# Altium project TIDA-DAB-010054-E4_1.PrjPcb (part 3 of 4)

## Sheet TIDA-DAB-010054-E4_GateDriverPrimHB2.SchDoc
size 431 x 279 mm; Date: Not shown in title block; ApprovedBy: Not shown in title block; CheckedBy: Not shown in title block; Author: Not shown in title block; CompanyName: Not shown in title block; Engineer: Not shown in title block; Organization: Not shown in title block; Address1: Not shown in title block; Address2: Not shown in title block; Address3: Not shown in title block; Address4: Not shown in title block; DocumentNumber: 1; Revision: Use project parameter SCH_Rev; SheetNumber: 6; SheetTotal: 11; PageSetup: Record=PageOptions¦CenterHorizontal=True¦CenterVertical=True¦PrintScale=1.00¦XCorrection=1.00¦YCorrection=1.00¦PrintKind=0¦BorderSize=5000000¦LeftOffset=0¦BottomOffset=0¦Orientation=2¦PaperLength=1000¦PaperWidth=1000¦Scale=100¦PaperSource=15¦PrintQuality=600¦MediaType=1¦DitherType=10¦PaperKind=Letter¦PrintScaleMode=1
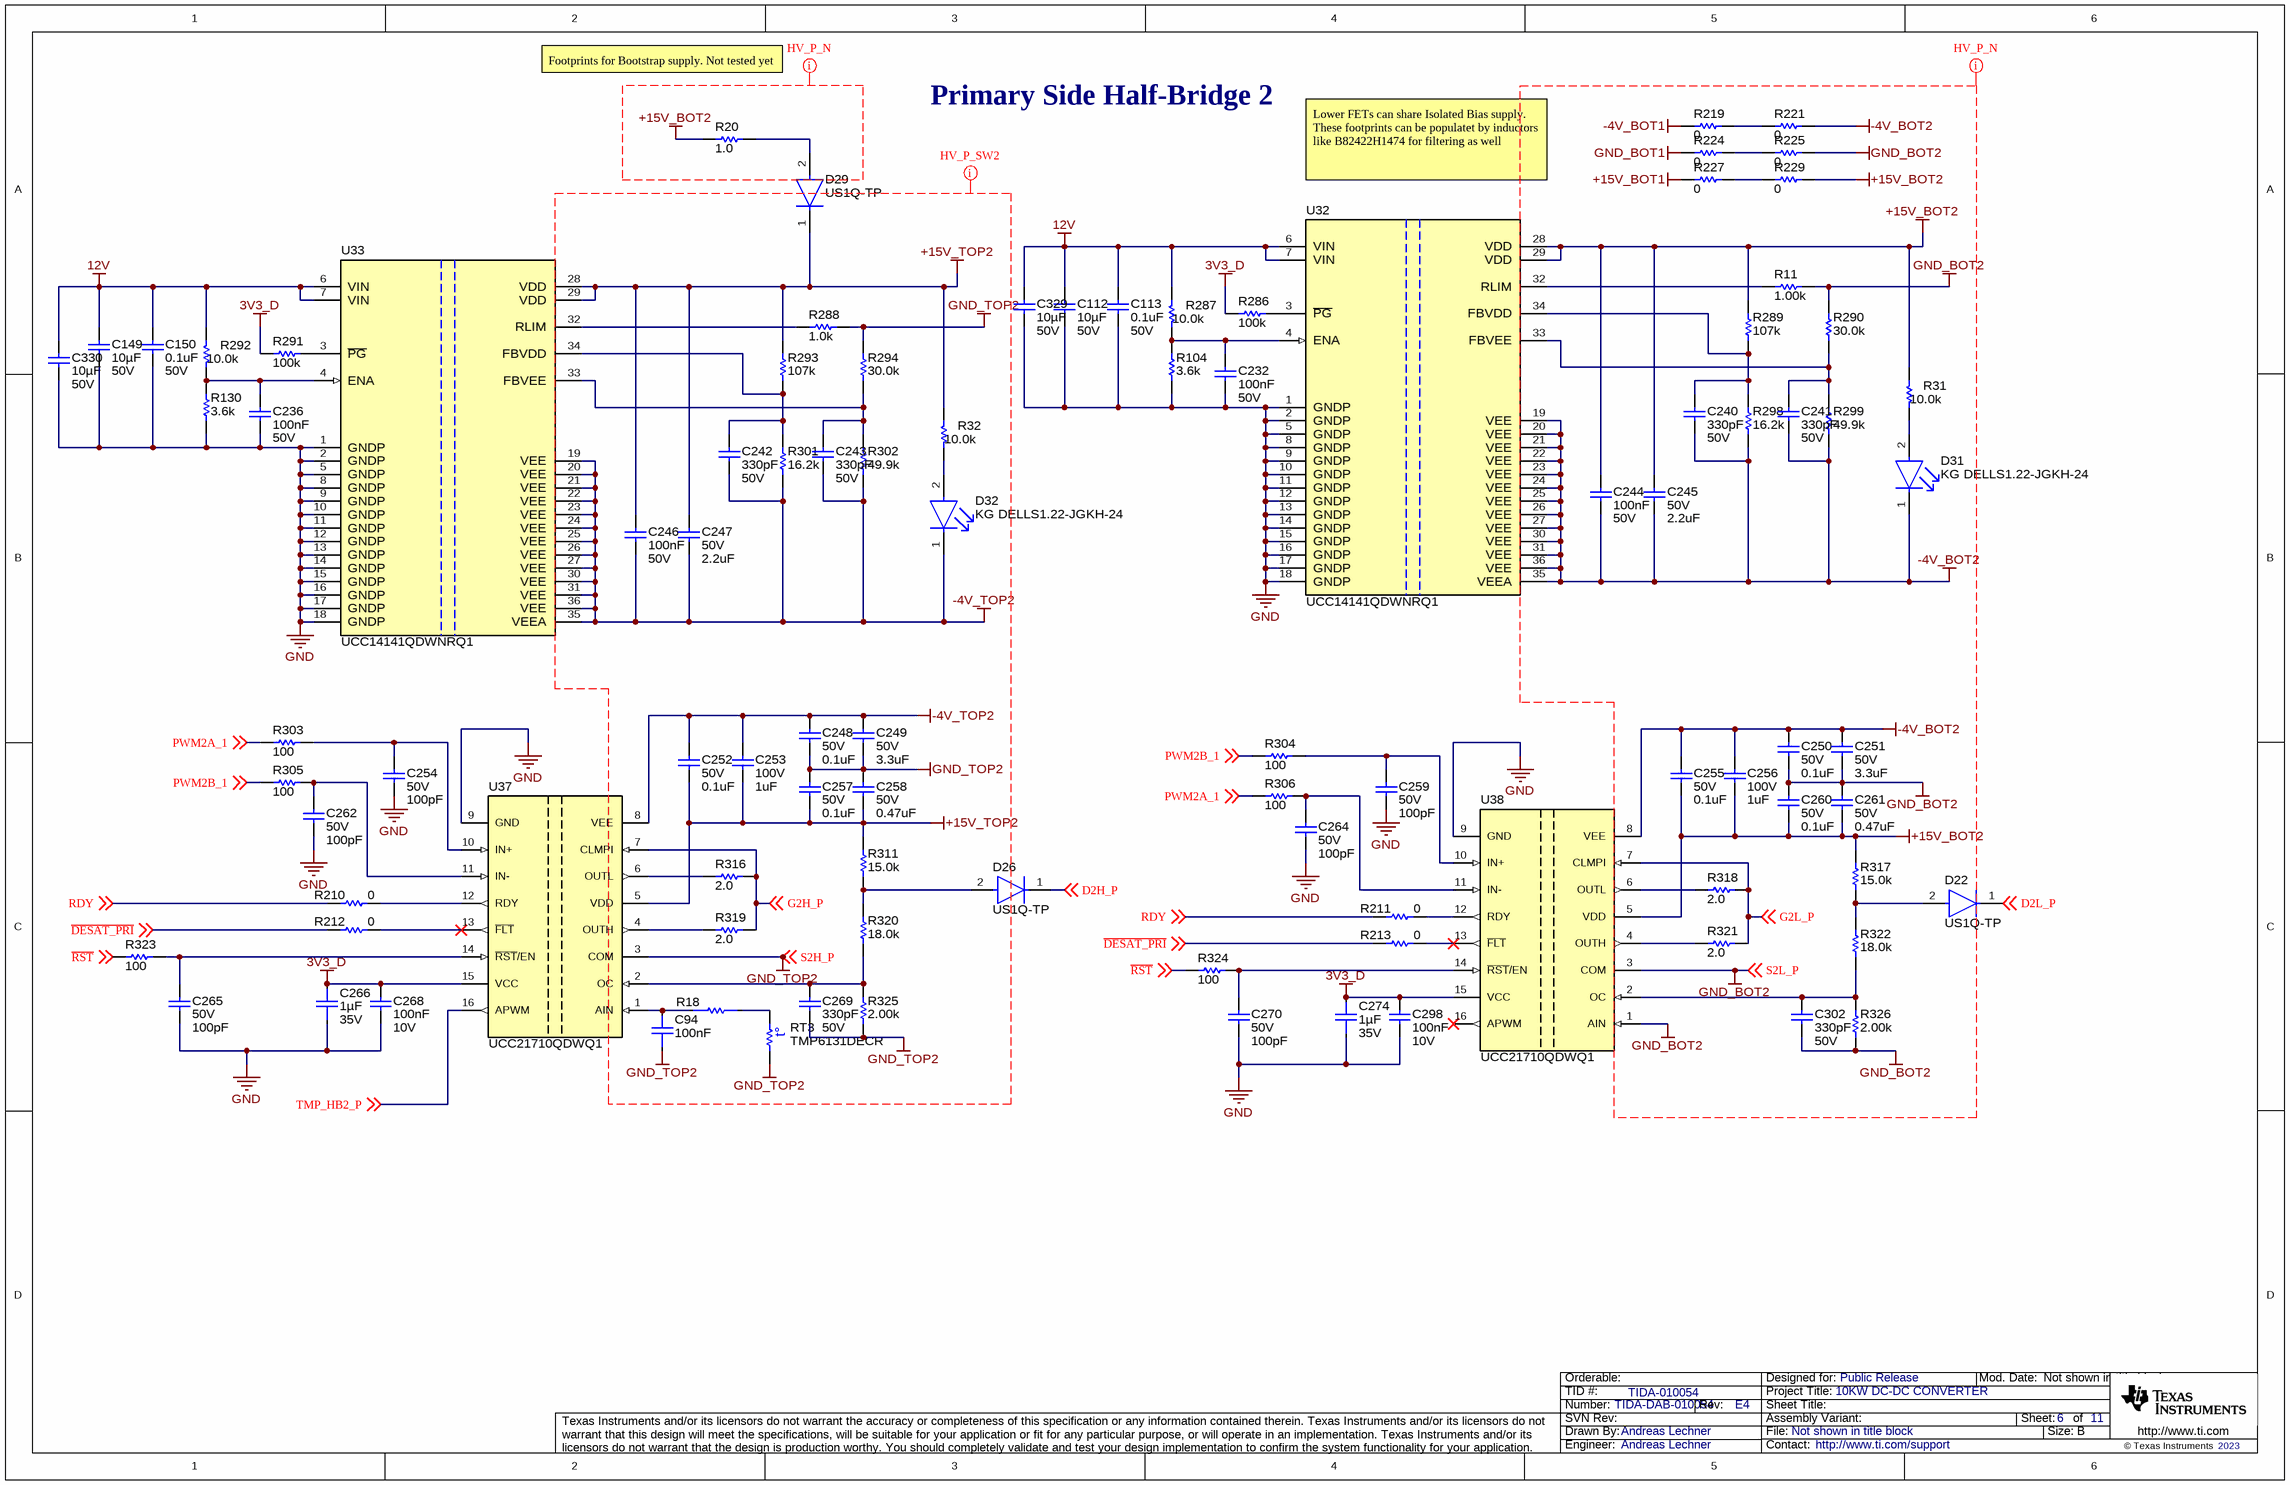
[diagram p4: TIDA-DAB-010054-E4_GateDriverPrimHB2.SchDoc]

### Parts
C94  Cap_F: 100nF  [FP-CL10B104KA8VPJC_0603-MFG]  (hidden comment: CL10B104KA8VPJC)
C112  ValueDisplayed: 10µF  VDC_V: 50V  [1206_190L]  (hidden comment: CGA5L1X7R1H106K160AC)
C113  value 0.1uF  VDC_V: 50V  [0603]  (hidden comment: CGA3E2X7R1H104K080AA)
C149  ValueDisplayed: 10µF  VDC_V: 50V  [1206_190L]  (hidden comment: CGA5L1X7R1H106K160AC)
C150  value 0.1uF  VDC_V: 50V  [0603]  (hidden comment: CGA3E2X7R1H104K080AA)
C232  Cap_F: 100nF  VDC_V: 50V  [0603]  (hidden comment: CGA3E2X7R1H104K080AA)
C236  Cap_F: 100nF  VDC_V: 50V  [0603]  (hidden comment: CGA3E2X7R1H104K080AA)
C240  Cap_F: 330pF  VDC_V: 50V  [0603]  (hidden comment: C0603C331K5RACTU)
C241  Cap_F: 330pF  VDC_V: 50V  [0603]  (hidden comment: C0603C331K5RACTU)
C242  Cap_F: 330pF  VDC_V: 50V  [0603]  (hidden comment: C0603C331K5RACTU)
C243  Cap_F: 330pF  VDC_V: 50V  [0603]  (hidden comment: C0603C331K5RACTU)
C244  Cap_F: 100nF  VDC_V: 50V  [0603]  (hidden comment: CGA3E2X7R1H104K080AA)
C245  VDC_V: 50V  ValueDisplayed: 2.2uF  [1206_180L]  (hidden comment: C3216X7R1H225K160AB)
C246  Cap_F: 100nF  VDC_V: 50V  [0603]  (hidden comment: CGA3E2X7R1H104K080AA)
C247  VDC_V: 50V  ValueDisplayed: 2.2uF  [1206_180L]  (hidden comment: C3216X7R1H225K160AB)
C248  VDC_V: 50V  ValueDisplayed: 0.1uF  [1206L]  (hidden comment: C1206C104K5RACTU)
C249  VDC_V: 50V  ValueDisplayed: 3.3uF  [1206_180L]  (hidden comment: C3216X5R1H335K160AB)
C250  VDC_V: 50V  ValueDisplayed: 0.1uF  [1206L]  (hidden comment: C1206C104K5RACTU)
C251  VDC_V: 50V  ValueDisplayed: 3.3uF  [1206_180L]  (hidden comment: C3216X5R1H335K160AB)
C252  VDC_V: 50V  ValueDisplayed: 0.1uF  [1206L]  (hidden comment: C1206C104K5RACTU)
C253  VDC_V: 100V  ValueDisplayed: 1uF  [1206_180L]  (hidden comment: C3216X7R2A105K160AA)
C254  VDC_V: 50V  ValueDisplayed: 100pF  [0603]  (hidden comment: C0603C101F5GACTU)
C255  VDC_V: 50V  ValueDisplayed: 0.1uF  [1206L]  (hidden comment: C1206C104K5RACTU)
C256  VDC_V: 100V  ValueDisplayed: 1uF  [1206_180L]  (hidden comment: C3216X7R2A105K160AA)
C257  VDC_V: 50V  ValueDisplayed: 0.1uF  [1206L]  (hidden comment: C1206C104K5RACTU)
C258  VDC_V: 50V  ValueDisplayed: 0.47uF  [1206_180L]  (hidden comment: C3216X7R1H474K160AA)
C259  VDC_V: 50V  ValueDisplayed: 100pF  [0603]  (hidden comment: C0603C101F5GACTU)
C260  VDC_V: 50V  ValueDisplayed: 0.1uF  [1206L]  (hidden comment: C1206C104K5RACTU)
C261  VDC_V: 50V  ValueDisplayed: 0.47uF  [1206_180L]  (hidden comment: C3216X7R1H474K160AA)
C262  VDC_V: 50V  ValueDisplayed: 100pF  [0603]  (hidden comment: C0603C101F5GACTU)
C264  VDC_V: 50V  ValueDisplayed: 100pF  [0603]  (hidden comment: C0603C101F5GACTU)
C265  VDC_V: 50V  ValueDisplayed: 100pF  [0603]  (hidden comment: C0603C101F5GACTU)
C266  Cap_F: 1µF  VDC_V: 35V  [FP-CL10B105KL9VPJC_0603-MFG]  (hidden comment: CL10B105KL9VPJC)
C268  Cap_F: 100nF  VDC_V: 10V  [0603]  (hidden comment: 0603ZC104KAT2A)
C269  Cap_F: 330pF  VDC_V: 50V  [0603]  (hidden comment: C0603C331K5RACTU)
C270  VDC_V: 50V  ValueDisplayed: 100pF  [0603]  (hidden comment: C0603C101F5GACTU)
C274  Cap_F: 1µF  VDC_V: 35V  [FP-CL10B105KL9VPJC_0603-MFG]  (hidden comment: CL10B105KL9VPJC)
C298  Cap_F: 100nF  VDC_V: 10V  [0603]  (hidden comment: 0603ZC104KAT2A)
C302  Cap_F: 330pF  VDC_V: 50V  [0603]  (hidden comment: C0603C331K5RACTU)
C329  ValueDisplayed: 10µF  VDC_V: 50V  [1206_190L]  (hidden comment: CGA5L1X7R1H106K160AC)
C330  ValueDisplayed: 10µF  VDC_V: 50V  [1206_190L]  (hidden comment: CGA5L1X7R1H106K160AC)
D22  US1Q-TP  [FP-US1Q-TP_SMA-MFG]
D26  US1Q-TP  [FP-US1Q-TP_SMA-MFG]
D29  US1Q-TP  [FP-US1Q-TP_SMA-MFG]
D31  KG DELLS1.22-JGKH-24  [FP-KG DELLS1.22-JGKH-24_0603-MFG]
D32  KG DELLS1.22-JGKH-24  [FP-KG DELLS1.22-JGKH-24_0603-MFG]
R11  ValueDisplayed: 1.00k  [0805_HV]  (hidden comment: ERJ-P06F1001V)
R18  CH0603-10RJFTA  [FP-CH0603-10RJFTA_0603-MFG]  (value not drawn)
R20  ValueDisplayed: 1.0  [1206]  (hidden comment: CRM1206-JW-1R0ELF)
R31  ValueDisplayed: 10.0k  [0603]  (hidden comment: CRCW060310K0FKEA)
R32  ValueDisplayed: 10.0k  [0603]  (hidden comment: CRCW060310K0FKEA)
R104  ValueDisplayed: 3.6k  [0603]  (hidden comment: RC0603JR-073K6L)
R130  ValueDisplayed: 3.6k  [0603]  (hidden comment: RC0603JR-073K6L)
R210  ValueDisplayed: 0  [0603S]  (hidden comment: RMCF0603ZT0R00)
R211  ValueDisplayed: 0  [0603S]  (hidden comment: RMCF0603ZT0R00)
R212  ValueDisplayed: 0  [0603S]  (hidden comment: RMCF0603ZT0R00)
R213  ValueDisplayed: 0  [0603S]  (hidden comment: RMCF0603ZT0R00)
R219  ValueDisplayed: 0  [1210]  (hidden comment: CRCW12100000Z0EA)
R221  ValueDisplayed: 0  [1210]  (hidden comment: CRCW12100000Z0EA)
R224  ValueDisplayed: 0  [1210]  (hidden comment: CRCW12100000Z0EA)
R225  ValueDisplayed: 0  [1210]  (hidden comment: CRCW12100000Z0EA)
R227  ValueDisplayed: 0  [1210]  (hidden comment: CRCW12100000Z0EA)
R229  ValueDisplayed: 0  [1210]  (hidden comment: CRCW12100000Z0EA)
R286  ValueDisplayed: 100k  [0603]  (hidden comment: CRCW0603100KJNEA)
R287  ValueDisplayed: 10.0k  [0603]  (hidden comment: CRCW060310K0FKEA)
R288  ValueDisplayed: 1.0k  [0603]  (hidden comment: RCA06031K00JNEA)
R289  ValueDisplayed: 107k  [0603]  (hidden comment: RT0603BRD07107KL)
R290  ValueDisplayed: 30.0k  [0603]  (hidden comment: RG1608P-303-B-T5)
R291  ValueDisplayed: 100k  [0603]  (hidden comment: CRCW0603100KJNEA)
R292  ValueDisplayed: 10.0k  [0603]  (hidden comment: CRCW060310K0FKEA)
R293  ValueDisplayed: 107k  [0603]  (hidden comment: RT0603BRD07107KL)
R294  ValueDisplayed: 30.0k  [0603]  (hidden comment: RG1608P-303-B-T5)
R298  ValueDisplayed: 16.2k  [0603]  (hidden comment: RT0603BRD0716K2L)
R299  ValueDisplayed: 49.9k  [0603]  (hidden comment: RT0603BRD0749K9L)
R301  ValueDisplayed: 16.2k  [0603]  (hidden comment: RT0603BRD0716K2L)
R302  ValueDisplayed: 49.9k  [0603]  (hidden comment: RT0603BRD0749K9L)
R303  ValueDisplayed: 100  [0603]  (hidden comment: CRCW0603100RJNEA)
R304  ValueDisplayed: 100  [0603]  (hidden comment: CRCW0603100RJNEA)
R305  ValueDisplayed: 100  [0603]  (hidden comment: CRCW0603100RJNEA)
R306  ValueDisplayed: 100  [0603]  (hidden comment: CRCW0603100RJNEA)
R311  ValueDisplayed: 15.0k  [0603]  (hidden comment: RC0603FR-0715KL)
R316  ValueDisplayed: 2.0  [1206]  (hidden comment: CRCW12062R00JNEA)
R317  ValueDisplayed: 15.0k  [0603]  (hidden comment: RC0603FR-0715KL)
R318  ValueDisplayed: 2.0  [1206]  (hidden comment: CRCW12062R00JNEA)
R319  ValueDisplayed: 2.0  [1206]  (hidden comment: CRCW12062R00JNEA)
R320  ValueDisplayed: 18.0k  [0603]  (hidden comment: ERJ3EKF1802V)
R321  ValueDisplayed: 2.0  [1206]  (hidden comment: CRCW12062R00JNEA)
R322  ValueDisplayed: 18.0k  [0603]  (hidden comment: ERJ3EKF1802V)
R323  ValueDisplayed: 100  [0603]  (hidden comment: CRCW0603100RJNEA)
R324  ValueDisplayed: 100  [0603]  (hidden comment: CRCW0603100RJNEA)
R325  ValueDisplayed: 2.00k  [0603]  (hidden comment: RC0603FR-072KL)
R326  ValueDisplayed: 2.00k  [0603]  (hidden comment: RC0603FR-072KL)
RT3  TMP6131DECR  [DEC0002A]
U32  UCC14141QDWNRQ1  [DWJ0036A-MFG]
U33  UCC14141QDWNRQ1  [DWJ0036A-MFG]
U37  UCC21710QDWQ1  [DW0016B_HV]
U38  UCC21710QDWQ1  [DW0016B_HV]

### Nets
3V3_D: C266.2 C268.2 C274.2 C298.2 R286.1 R291.1 U37.15(VCC) U38.15(VCC)
12V: C112.1 C113.1 C149.1 C150.1 C329.1 C330.1 R287.2 R292.2 U32.6(VIN) U32.7(VIN) U33.6(VIN) U33.7(VIN)
+15V_BOT1: R227.1
+15V_BOT2: C244.1 C245.1 C255.2 C256.2 C260.2 C261.2 R20.1 R31.2 R229.2 R289.2 R317.2 U32.28(VDD) U32.29(VDD) U38.5(VDD)
+15V_TOP2: C246.1 C247.1 C252.2 C253.2 C257.2 C258.2 D29.1(CATHODE) R32.2 R293.2 R311.2 U33.28(VDD) U33.29(VDD) U37.5(VDD)
-4V_BOT1: R219.1
-4V_BOT2: C240.2 C241.2 C244.2 C245.2 C250.1 C251.1 C255.1 C256.1 D31.1(CATHODE) R221.2 R298.1 R299.1 U32.19(VEE) U32.20(VEE) U32.21(VEE) U32.22(VEE) U32.23(VEE) U32.24(VEE) U32.25(VEE) U32.26(VEE) U32.27(VEE) U32.30(VEE) U32.31(VEE) U32.35(VEEA) U32.36(VEE) U38.8(VEE)
-4V_TOP2: C242.2 C243.2 C246.2 C247.2 C248.1 C249.1 C252.1 C253.1 D32.1(CATHODE) R301.1 R302.1 U33.19(VEE) U33.20(VEE) U33.21(VEE) U33.22(VEE) U33.23(VEE) U33.24(VEE) U33.25(VEE) U33.26(VEE) U33.27(VEE) U33.30(VEE) U33.31(VEE) U33.35(VEEA) U33.36(VEE) U37.8(VEE)
GND: C112.2 C113.2 C149.2 C150.2 C232.2 C236.2 C254.2 C259.2 C262.2 C264.2 C265.2 C266.1 C268.1 C270.2 C274.1 C298.1 C329.2 C330.2 R104.1 R130.1 U32.1(GNDP) U32.2(GNDP) U32.5(GNDP) U32.8(GNDP) U32.9(GNDP) U32.10(GNDP) U32.11(GNDP) U32.12(GNDP) U32.13(GNDP) U32.14(GNDP) U32.15(GNDP) U32.16(GNDP) U32.17(GNDP) U32.18(GNDP) U33.1(GNDP) U33.2(GNDP) U33.5(GNDP) U33.8(GNDP) U33.9(GNDP) U33.10(GNDP) U33.11(GNDP) U33.12(GNDP) U33.13(GNDP) U33.14(GNDP) U33.15(GNDP) U33.16(GNDP) U33.17(GNDP) U33.18(GNDP) U37.9(GND) U38.9(GND)
GND_BOT1: R224.1
GND_BOT2: C250.2 C251.2 C260.1 C261.1 C302.2 R11.2 R225.2 R290.2 R326.1 U38.1(AIN) U38.3(COM) ; off-sheet S2L_P  [also labelled S2L_P]
GND_TOP2: C94.1 C248.2 C249.2 C257.1 C258.1 C269.2 R288.2 R294.2 R325.1 RT3.1 U37.3(COM) ; off-sheet S2H_P  [also labelled S2H_P]
~{DESAT_PRI}: R212.1 R213.1 ; off-sheet ~{DESAT_PRI}
~{RST}: R323.1 R324.1 ; off-sheet ~{RST}
D2H_P: D26.1(CATHODE) ; off-sheet D2H_P  [project net D1H_P]
D2L_P: D22.1(CATHODE) ; off-sheet D2L_P
G2H_P: R316.2 R319.2 U37.7(CLMPI) ; off-sheet G2H_P
G2L_P: R318.2 R321.2 U38.7(CLMPI) ; off-sheet G2L_P
PWM2A_1: R303.1 R306.1 ; off-sheet PWM2A_1
PWM2B_1: R304.1 R305.1 ; off-sheet PWM2B_1
RDY: R210.1 R211.1 ; off-sheet RDY
TMP_HB2_P: U37.16(APWM) ; off-sheet TMP_HB2_P
NetC94_2: C94.2 R18.1 U37.1(AIN)
NetC232_1: C232.1 R104.2 R287.1 U32.4(ENA)
NetC236_1: C236.1 R130.2 R292.1 U33.4(ENA)
NetC240_1: C240.1 R289.1 R298.2 U32.34(FBVDD)
NetC241_1: C241.1 R290.1 R299.2 U32.33(FBVEE)
NetC242_1: C242.1 R293.1 R301.2 U33.34(FBVDD)
NetC243_1: C243.1 R294.1 R302.2 U33.33(FBVEE)
NetC254_1: C254.1 R303.2 U37.10(IN+)
NetC259_1: C259.1 R304.2 U38.10(IN+)
NetC262_1: C262.1 R305.2 U37.11(IN-)
NetC264_1: C264.1 R306.2 U38.11(IN-)
NetC265_1: C265.1 R323.2 U37.14(~{RST}/EN)
NetC269_1: C269.1 R320.1 R325.2 U37.2(OC)
NetC270_1: C270.1 R324.2 U38.14(~{RST}/EN)
NetC302_1: C302.1 R322.1 R326.2 U38.2(OC)
NetD22_2: D22.2(ANODE) R317.1 R322.2
NetD26_2: D26.2(ANODE) R311.1 R320.2
NetD29_2: D29.2(ANODE) R20.2
NetD31_2: D31.2(ANODE) R31.1
NetD32_2: D32.2(ANODE) R32.1
NetR11_1: R11.1 U32.32(RLIM)
NetR18_2: R18.2 RT3.2
NetR210_2: R210.2 U37.12(RDY)
NetR211_2: R211.2 U38.12(RDY)
NetR212_2: R212.2 U37.13(~{FLT})
NetR213_2: R213.2 U38.13(~{FLT})
NetR219_2: R219.2 R221.1
NetR224_2: R224.2 R225.1
NetR227_2: R227.2 R229.1
NetR286_2: R286.2 U32.3(~{PG})
NetR288_1: R288.1 U33.32(RLIM)
NetR291_2: R291.2 U33.3(~{PG})
NetR316_1: R316.1 U37.6(OUTL)
NetR318_1: R318.1 U38.6(OUTL)
NetR319_1: R319.1 U37.4(OUTH)
NetR321_1: R321.1 U38.4(OUTH)

Not connected (* = marked no-connect by the designer): U38 16(APWM)*

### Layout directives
net class HV_P_SW2: +15V_TOP2, -4V_TOP2, G2H_P, GND_TOP2, S2H_P
net class HV_P_N: +15V_BOT1, +15V_BOT2, -4V_BOT1, -4V_BOT2, G2L_P, GND, GND_BOT1, GND_BOT2, S2L_P

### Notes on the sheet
- Footprints for Bootstrap supply. Not tested yet
- Primary Side Half-Bridge 2
- Lower FETs can share Isolated Bias supply.
  These footprints can be populatet by inductors  like B82422H1474 for filtering as well

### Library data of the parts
C94 = CMP-0121051-1: Automotive CAP, 100㎋, 25V, ±10%, X7R, 0603, 5mm Bending; Manufacturer: Samsung; AEC Grade: Grade 1; AEC Qualified: Yes; SizeZ_mm: 0.9mm; TempCo: 15%; Value: 100nF
C112 C149 C329 C330 = CMP-0085950-1: CAP, CERM, 10 µF, 50 V,+/- 10%, X7R, AEC-Q200 Grade 1, 1206; Manufacturer: TDK; SizeZ_mm: 1.9; Value: 10uF; Cap_Case: 1206; AEC Grade: 1; TaMin_C: -55°C; U/M: EA; SizeArea_mm2: 5.12; TaMax_C: 125°C; AEC Qualified: Y; AEC Category: Q200; SizeX_mm: 3.2; SizeY_mm: 1.6; Polarized: N; SizeAreaWB_mm2: 10.92
C113 C150 = CMP-0007078-4: CAP, CERM, 0.1 uF, 50 V, +/- 10%, X7R, AEC-Q200 Grade 1, 0603; Manufacturer: TDK; TaMin_C: -55°C; ESR_ohm: 29.6m; Polarized: N; SizeAreaWB_mm2: 4.68; Value1: 0.0296 ohm; U/M: EA; TaMax_C: 125°C; SizeZ_mm: 1; SizeX_mm: 1.6; SizeY_mm: 0.8; SizeArea_mm2: 1.28; AEC Qualified: Y; Cap_F: 100nF; IRMS_A: 971.99mA; AEC Category: Q200
C232 C236 C244 C246 = CMP-0007078-4: CAP, CERM, 0.1 uF, 50 V, +/- 10%, X7R, AEC-Q200 Grade 1, 0603; Manufacturer: TDK; TaMin_C: -55°C; ESR_ohm: 29.6m; Polarized: N; SizeAreaWB_mm2: 4.68; Value1: 0.0296 ohm; U/M: EA; Value: 0.1uF; TaMax_C: 125°C; SizeZ_mm: 1; SizeX_mm: 1.6; SizeY_mm: 0.8; SizeArea_mm2: 1.28; AEC Qualified: Y; IRMS_A: 971.99mA; AEC Category: Q200
C240-C243 C269 C302 = CMP-0006921-4: CAP, CERM, 330 pF, 50 V, +/- 10%, X7R, 0603; Manufacturer: Kemet; TaMin_C: -55°C; Polarized: N; SizeAreaWB_mm2: 4.68; Value1: Unknown; U/M: EA; Value: 330pF; TaMax_C: 125°C; SizeZ_mm: 1; SizeX_mm: 1.6; SizeY_mm: 0.8; SizeArea_mm2: 1.28; AEC Category: Q200
C245 C247 = CMP-0008698-2: CAP, CERM, 2.2 uF, 50 V, +/- 10%, X7R, 1206; Manufacturer: TDK; TaMin_C: -55°C; ESR_ohm: 5.887m; Polarized: N; SizeAreaWB_mm2: 10.92; Value1: 0.005887 ohm; U/M: EA; Value: 2.2uF; TaMax_C: 125°C; SizeZ_mm: 1.8; SizeX_mm: 3.2; SizeY_mm: 1.6; Cap_Case: 1206_180; SizeArea_mm2: 5.12; Cap_F: 2.2µF; IRMS_A: 2.9923A; AEC Category: Q200
C248 C250 C252 C255 C257 C260 = CMP-0008586-2: CAP, CERM, 0.1 uF, 50 V, +/- 10%, X7R, 1206; Manufacturer: Kemet; TaMin_C: -55°C; ESR_ohm: 59m; Polarized: N; SizeAreaWB_mm2: 10.92; Value1: 0.059 ohm; U/M: EA; Value: 0.1uF; TaMax_C: 125°C; SizeZ_mm: 1.35; SizeX_mm: 3.2; SizeY_mm: 1.6; Cap_Case: 1206; SizeArea_mm2: 5.12; Cap_F: 100nF; IRMS_A: 1.2A; AEC Category: Q200
C249 C251 = CMP-0008661-2: CAP, CERM, 3.3 uF, 50 V, +/- 10%, X5R, 1206; Manufacturer: TDK; TaMin_C: -55°C; ESR_ohm: 4.773m; Polarized: N; SizeAreaWB_mm2: 10.92; Value1: 0.004773 ohm; U/M: EA; Value: 3.3uF; TaMax_C: 85°C; SizeZ_mm: 1.8; SizeX_mm: 3.2; SizeY_mm: 1.6; Cap_Case: 1206_180; SizeArea_mm2: 5.12; Cap_F: 3.3µF; IRMS_A: 3.3221A; AEC Category: Q200
C253 C256 = CMP-0008710-2: CAP, CERM, 1 uF, 100 V, +/- 10%, X7R, 1206; Manufacturer: TDK; TaMin_C: -55°C; ESR_ohm: 4.575m; Polarized: N; SizeAreaWB_mm2: 10.92; Value1: 0.004575 ohm; U/M: EA; Value: 1uF; TaMax_C: 125°C; SizeZ_mm: 1.8; SizeX_mm: 3.2; SizeY_mm: 1.6; Cap_Case: 1206_180; SizeArea_mm2: 5.12; Cap_F: 1µF; IRMS_A: 3.3964A; AEC Category: Q200
C254 C259 C262 C264 C265 C270 = CMP-0080091-1: CAP, CERM, 100 pF, 50 V,+/- 1%, C0G/NP0, 0603; Manufacturer: Kemet; SizeAreaWB_mm2: 4.68; SizeArea_mm2: 1.28; AEC Qualified: N; AEC Category: Q200; Value: 100pF; TaMax_C: 125°C; SizeZ_mm: 1; Green_REACh: Passed; TaMin_C: -55°C; SizeY_mm: 0.8; Green_Lifecycle: Active; U/M: EA; SizeX_mm: 1.6
C258 C261 = CMP-0008701-2: CAP, CERM, 0.47 uF, 50 V, +/- 10%, X7R, 1206; Manufacturer: TDK; TaMin_C: -55°C; ESR_ohm: 9.426m; Polarized: N; SizeAreaWB_mm2: 10.92; Value1: 0.009426 ohm; U/M: EA; Value: 0.47uF; TaMax_C: 125°C; SizeZ_mm: 1.8; SizeX_mm: 3.2; SizeY_mm: 1.6; Cap_Case: 1206_180; SizeArea_mm2: 5.12; Cap_F: 470nF; IRMS_A: 2.3705A; AEC Category: Q200
C266 C274 = CMP-0121053-1: Automotive CAP, 1㎌, 35V, ±10%, X7R, 0603, 5mm Bending; Manufacturer: Samsung; AEC Grade: Grade 1; AEC Qualified: Yes; SizeZ_mm: 1mm; TempCo: 15%; ValueDisplayed: 1uF; Value: 1µF
C268 C298 = CMP-0006815-4: CAP, CERM, 0.1 uF, 10 V, +/- 10%, X7R, 0603; Manufacturer: AVX; TaMin_C: -55°C; Polarized: N; SizeAreaWB_mm2: 4.68; Value1: Unknown; U/M: EA; Value: 0.1uF; TaMax_C: 125°C; SizeZ_mm: 1; SizeX_mm: 1.6; SizeY_mm: 0.8; SizeArea_mm2: 1.28; AEC Category: Q200
D22 D26 D29 = CMP-0095286-1: Diode Standard 1200 V 1A Surface Mount DO-214AC (SMA); Manufacturer: MCC; Cap_F: 45pF; Max Surge Forward Current: 30A; SizeZ_mm: 2.44mm; TJmax_C: 150°C; Vr_V: 1.2kV; Peak Reverse Current: 5uA; AEC Qualified: No
D31 D32 = CMP-0093310-1: Standard LEDs - SMD Green TOPLED E 1608; Manufacturer: Osram Opto; AEC Grade: Grade 2; LambdaP: 572nm; SizeZ_mm: 0.7mm; LuminousFlux_PhiV: 0.016-0.0295lm; Luminous Intensity: 4.5-9.7mcd; LambdaD: 570nm; Tjmax_C: 125°C; Angle: 120°; Led Orientation: Top View; Forward Current: 2mA; Vf_V: 1.8V; AEC Qualified: Yes; Vr_V: 12V
R11 = CMP-0021848-2: RES, 1.00 k, 1%, 0.25 W, 0805; Manufacturer: Panasonic; Power_W: 250mW; TempCo: 100 ppm/C; Value_Code: 1k00; U/M: EA; Value: 1.00k; EIA_Code: E96; Res_ohm: 1k; SizeX_mm: 2; SizeY_mm: 1.25; SizeZ_mm: 1.45; Value2: 0.25W; SizeArea_mm2: 2.5; VDC_V: 400V; AEC Category: Q200
R18 = CMP-0091849-1: Res Thin Film 0603 10Ohm 5% 1/8W ±100ppm/°C Molded T/R; Manufacturer: Vishay; SizeZ_mm: 0.627mm; Power_W: 125mW; AEC Qualified: No; Value: 10; VDC_V: 50V
R20 = CMP-0018745-2: RES, 1.0, 5%, 0.5 W, 1206; Manufacturer: Bourns; Power_W: 500mW; TempCo: 150 ppm/C; Value_Code: 1R00; U/M: EA; Value: 1.0; EIA_Code: E24; Res_ohm: 1; SizeX_mm: 3.2; SizeY_mm: 1.6; SizeZ_mm: 1.35; Value2: 0.5W; SizeArea_mm2: 5.12; VDC_V: 1V; AEC Category: Q200
R31 R32 R287 R292 = CMP-0021998-4: RES, 10.0 k, 1%, 0.1 W, AEC-Q200 Grade 0, 0603; Manufacturer: Vishay-Dale; Value: 10.0k; Res_ohm: 10k; Value_Code: 10k0; Power_W: 100mW; Value2: 0.1W; VDC_V: 75V; TempCo: 100 ppm/C; SizeArea_mm2: 1.28; SizeX_mm: 1.6; SizeY_mm: 0.8; SizeZ_mm: 1; EIA_Code: E96; AEC Category: Q200; AEC Qualified: Y; AEC Grade: 0
R104 R130 = CMP-0025919-5: RES, 3.6 k, 5%, 0.1 W, 0603; Manufacturer: Yageo; Power_W: 100mW; TempCo: 100 ppm/C; Value_Code: 3k60; Value: 3.6k; EIA_Code: E24; SizeX_mm: 1.6; SizeY_mm: 0.8; SizeZ_mm: 1; Value2: 0.1W; SizeArea_mm2: 1.28; AEC Qualified: N; VDC_V: 75V; AEC Category: Q200; SizeAreaWB_mm2: 4.68
R210-R213 = CMP-0023343-3: RES, 0, 1%, 0.1 W, AEC-Q200 Grade 0, 0603; Manufacturer: Stackpole Electronics Inc; Power_W: 100mW; TempCo: ppm/C; U/M: EA; Value: 0; SizeX_mm: 1.6; SizeY_mm: 0.8; SizeZ_mm: 1; Value2: 0.1W; SizeArea_mm2: 1.28; CompType: Resistor; AEC Qualified: Y; AEC Category: Q200
R219 R221 R224 R225 R227 R229 = CMP-0015016-3: RES, 0, 1%, 0.5 W, AEC-Q200 Grade 0, 1210; Manufacturer: Vishay-Dale; Power_W: 500mW; TempCo: ppm/C; SizeAreaWB_mm2: 14.7; Value: 0; SizeX_mm: 3.2; SizeY_mm: 2.5; SizeZ_mm: 1.35; Value2: 0.5W; SizeArea_mm2: 8; AEC Qualified: Y; AEC Category: Q200
R286 R291 = CMP-0025698-4: RES, 100 k, 5%, 0.1 W, AEC-Q200 Grade 0, 0603; Manufacturer: Vishay-Dale; Power_W: 100mW; TempCo: 200 ppm/C; Value: 100k; EIA_Code: E24; SizeX_mm: 1.6; SizeY_mm: 0.8; SizeZ_mm: 1; Value2: 0.1W; SizeArea_mm2: 1.28; AEC Qualified: Y; VDC_V: 75V; AEC Category: Q200; AEC Grade: 0
R288 = CMP-0025946-3: RES, 1.0 k, 5%, 0.1 W, AEC-Q200 Grade 0, 0603; Manufacturer: Vishay-Dale; Power_W: 100mW; TempCo: 200 ppm/C; Value_Code: 1k00; U/M: EA; Value: 1.0k; EIA_Code: E24; Res_ohm: 1k; SizeX_mm: 1.6; SizeY_mm: 0.8; SizeZ_mm: 1; Value2: 0.1W; SizeArea_mm2: 1.28; AEC Qualified: Y; VDC_V: 75V; AEC Grade: 0; AEC Category: Q200
R289 R293 = CMP-0023642-3: RES, 107 k, 0.1%, 0.1 W, 0603; Manufacturer: Yageo America; Power_W: 100mW; TempCo: 25 ppm/C; U/M: EA; Value: 107k; EIA_Code: E192; SizeX_mm: 1.6; SizeY_mm: 0.8; SizeZ_mm: 1; Value2: 0.1W; SizeArea_mm2: 1.28; VDC_V: 75V; AEC Category: Q200
R290 R294 = CMP-0023508-3: RES, 30.0 k, 0.1%, 0.1 W, 0603; Manufacturer: Susumu Co Ltd; Power_W: 100mW; TempCo: 25 ppm/C; Value_Code: 30k0; U/M: EA; Value: 30.0k; Res_ohm: 30k; SizeX_mm: 1.6; SizeY_mm: 0.8; SizeZ_mm: 1; Value2: 0.1W; SizeArea_mm2: 1.28; VDC_V: 75V; AEC Category: Q200
R298 R301 = CMP-0023798-3: RES, 16.2 k, 0.1%, 0.1 W, 0603; Manufacturer: Yageo America; Power_W: 100mW; TempCo: 25 ppm/C; Value_Code: 16k2; U/M: EA; Value: 16.2k; EIA_Code: E192; SizeX_mm: 1.6; SizeY_mm: 0.8; SizeZ_mm: 1; Value2: 0.1W; SizeArea_mm2: 1.28; VDC_V: 75V; AEC Category: Q200
R299 R302 = CMP-0024283-3: RES, 49.9 k, 0.1%, 0.1 W, 0603; Manufacturer: Yageo America; Power_W: 100mW; TempCo: 25 ppm/C; Value_Code: 49k9; U/M: EA; Value: 49.9k; EIA_Code: E192; SizeX_mm: 1.6; SizeY_mm: 0.8; SizeZ_mm: 1; Value2: 0.1W; SizeArea_mm2: 1.28; VDC_V: 75V; AEC Category: Q200
R303-R306 R323 R324 = CMP-0025700-4: RES, 100, 5%, 0.1 W, AEC-Q200 Grade 0, 0603; Manufacturer: Vishay-Dale; Power_W: 100mW; TempCo: 200 ppm/C; Value_Code: 100R; Value: 100; EIA_Code: E24; SizeX_mm: 1.6; SizeY_mm: 0.8; SizeZ_mm: 1; Value2: 0.1W; SizeArea_mm2: 1.28; AEC Qualified: Y; VDC_V: 75V; AEC Category: Q200; AEC Grade: 0
R311 R317 = CMP-0022816-5: RES, 15.0 k, 1%, 0.1 W, 0603; Manufacturer: Yageo; Power_W: 100mW; TempCo: 100 ppm/C; Value_Code: 15k0; Value: 15.0k; EIA_Code: E96; Res_ohm: 15k; SizeX_mm: 1.6; SizeY_mm: 0.8; SizeZ_mm: 1; Value2: 0.1W; SizeArea_mm2: 1.28; AEC Qualified: N; VDC_V: 75V; AEC Category: Q200; SizeAreaWB_mm2: 4.68
R316 R318 R319 R321 = CMP-0018648-3: RES, 2.0, 5%, 0.25 W, AEC-Q200 Grade 0, 1206; Manufacturer: Vishay-Dale; Power_W: 250mW; TempCo: 200 ppm/C; Value_Code: 2R00; Value: 2.0; EIA_Code: E24; Res_ohm: 2; SizeX_mm: 3.2; SizeY_mm: 1.6; SizeZ_mm: 1.35; Value2: 0.25W; SizeArea_mm2: 5.12; AEC Qualified: Y; VDC_V: 200V; AEC Category: Q200; AEC Grade: 0
R320 R322 = CMP-0078662-1: RES, 18.0 k, 1%, 0.1 W, AEC-Q200 Grade 0, 0603; Manufacturer: Panasonic; Power_W: 100mW; TempCo: 100 ppm/C; Value_Code: 18k0; Value: 18.0k; Res_ohm: 18k; SizeX_mm: 1.6; SizeY_mm: 0.8; SizeZ_mm: 1; Value2: 0.1W; SizeArea_mm2: 1.28; AEC Qualified: Y; AEC Grade: 0; AEC Category: Q200
R325 R326 = CMP-0023000-5: RES, 2.00 k, 1%, 0.1 W, 0603; Manufacturer: Yageo; Power_W: 100mW; TempCo: 100 ppm/C; Value_Code: 2k00; Value: 2.00k; EIA_Code: E96; Res_ohm: 2k; SizeX_mm: 1.6; SizeY_mm: 0.8; SizeZ_mm: 1; Value2: 0.1W; SizeArea_mm2: 1.28; AEC Qualified: N; VDC_V: 75V; AEC Category: Q200; SizeAreaWB_mm2: 4.68
RT3 = CMP-0084566-1: Thermistor, DEC0002A (X1SON-2); Alternate Manufacturer: Texas Instruments; Alternate PartNumber: TMP6131DECT; CompType: IC; AEC Category: Q200; SizeX_mm: 1; AEC Qualified: N; SizeZ_mm: 0.5; SizeArea_mm2: 0.6; SizeAreaWB_mm2: 3.2
U32 U33 = CMP-0034067-2: Automotive 1.5-W, 12-V VIN, 25-V VOUT, High-Density, > 5 kVRMS, Isolated DC/DC Module; Manufacturer: Texas Instruments; SizeZ_mm: 3.55mm; AEC Qualified: Yes; AEC Grade: Grade 1; Max Supply Voltage: 18V; Min Supply Voltage: 8V; Nominal Supply Current: 200-270mA; Number Of Outputs: 2; Output Type: AdjustableProgrammable; Output Voltage: 18-25V; Standoff Height: 0.1mm; Switching Frequency: 16MHz; TaMax_C: +125°C; TaMin_C: -40°C; TJmax_C: +150°C; AEC Category: Q200; CompType: IC
U37 U38 = CMP-0080534-2: Single Channel Isolated Gate Driver for SiC/IGBT with Advanced Protection and High-CMTI, DW0016B (SOIC-16); Manufacturer: Texas Instruments; Alternate PartNumber: UCC21710QDWRQ1; SizeY_mm: 10.3; CompType: IC; AEC Qualified: Y; SizeArea_mm2: 107.12; SizeAreaWB_mm2: 152.52; SizeZ_mm: 2.65; SizeX_mm: 10.4; AEC Category: Q200

## Sheet TIDA-DAB-010054-E4_GateDriverSecHB1.SchDoc
size 431 x 279 mm; Date: Not shown in title block; ApprovedBy: Not shown in title block; CheckedBy: Not shown in title block; Author: Not shown in title block; CompanyName: Not shown in title block; Engineer: Not shown in title block; Organization: Not shown in title block; Address1: Not shown in title block; Address2: Not shown in title block; Address3: Not shown in title block; Address4: Not shown in title block; DocumentNumber: 1; Revision: Use project parameter SCH_Rev; SheetNumber: 7; SheetTotal: 11; PageSetup: Record=PageOptions¦CenterHorizontal=True¦CenterVertical=True¦PrintScale=1.00¦XCorrection=1.00¦YCorrection=1.00¦PrintKind=0¦BorderSize=5000000¦LeftOffset=0¦BottomOffset=0¦Orientation=2¦PaperLength=1000¦PaperWidth=1000¦Scale=100¦PaperSource=15¦PrintQuality=600¦MediaType=1¦DitherType=10¦PaperKind=Letter¦PrintScaleMode=1
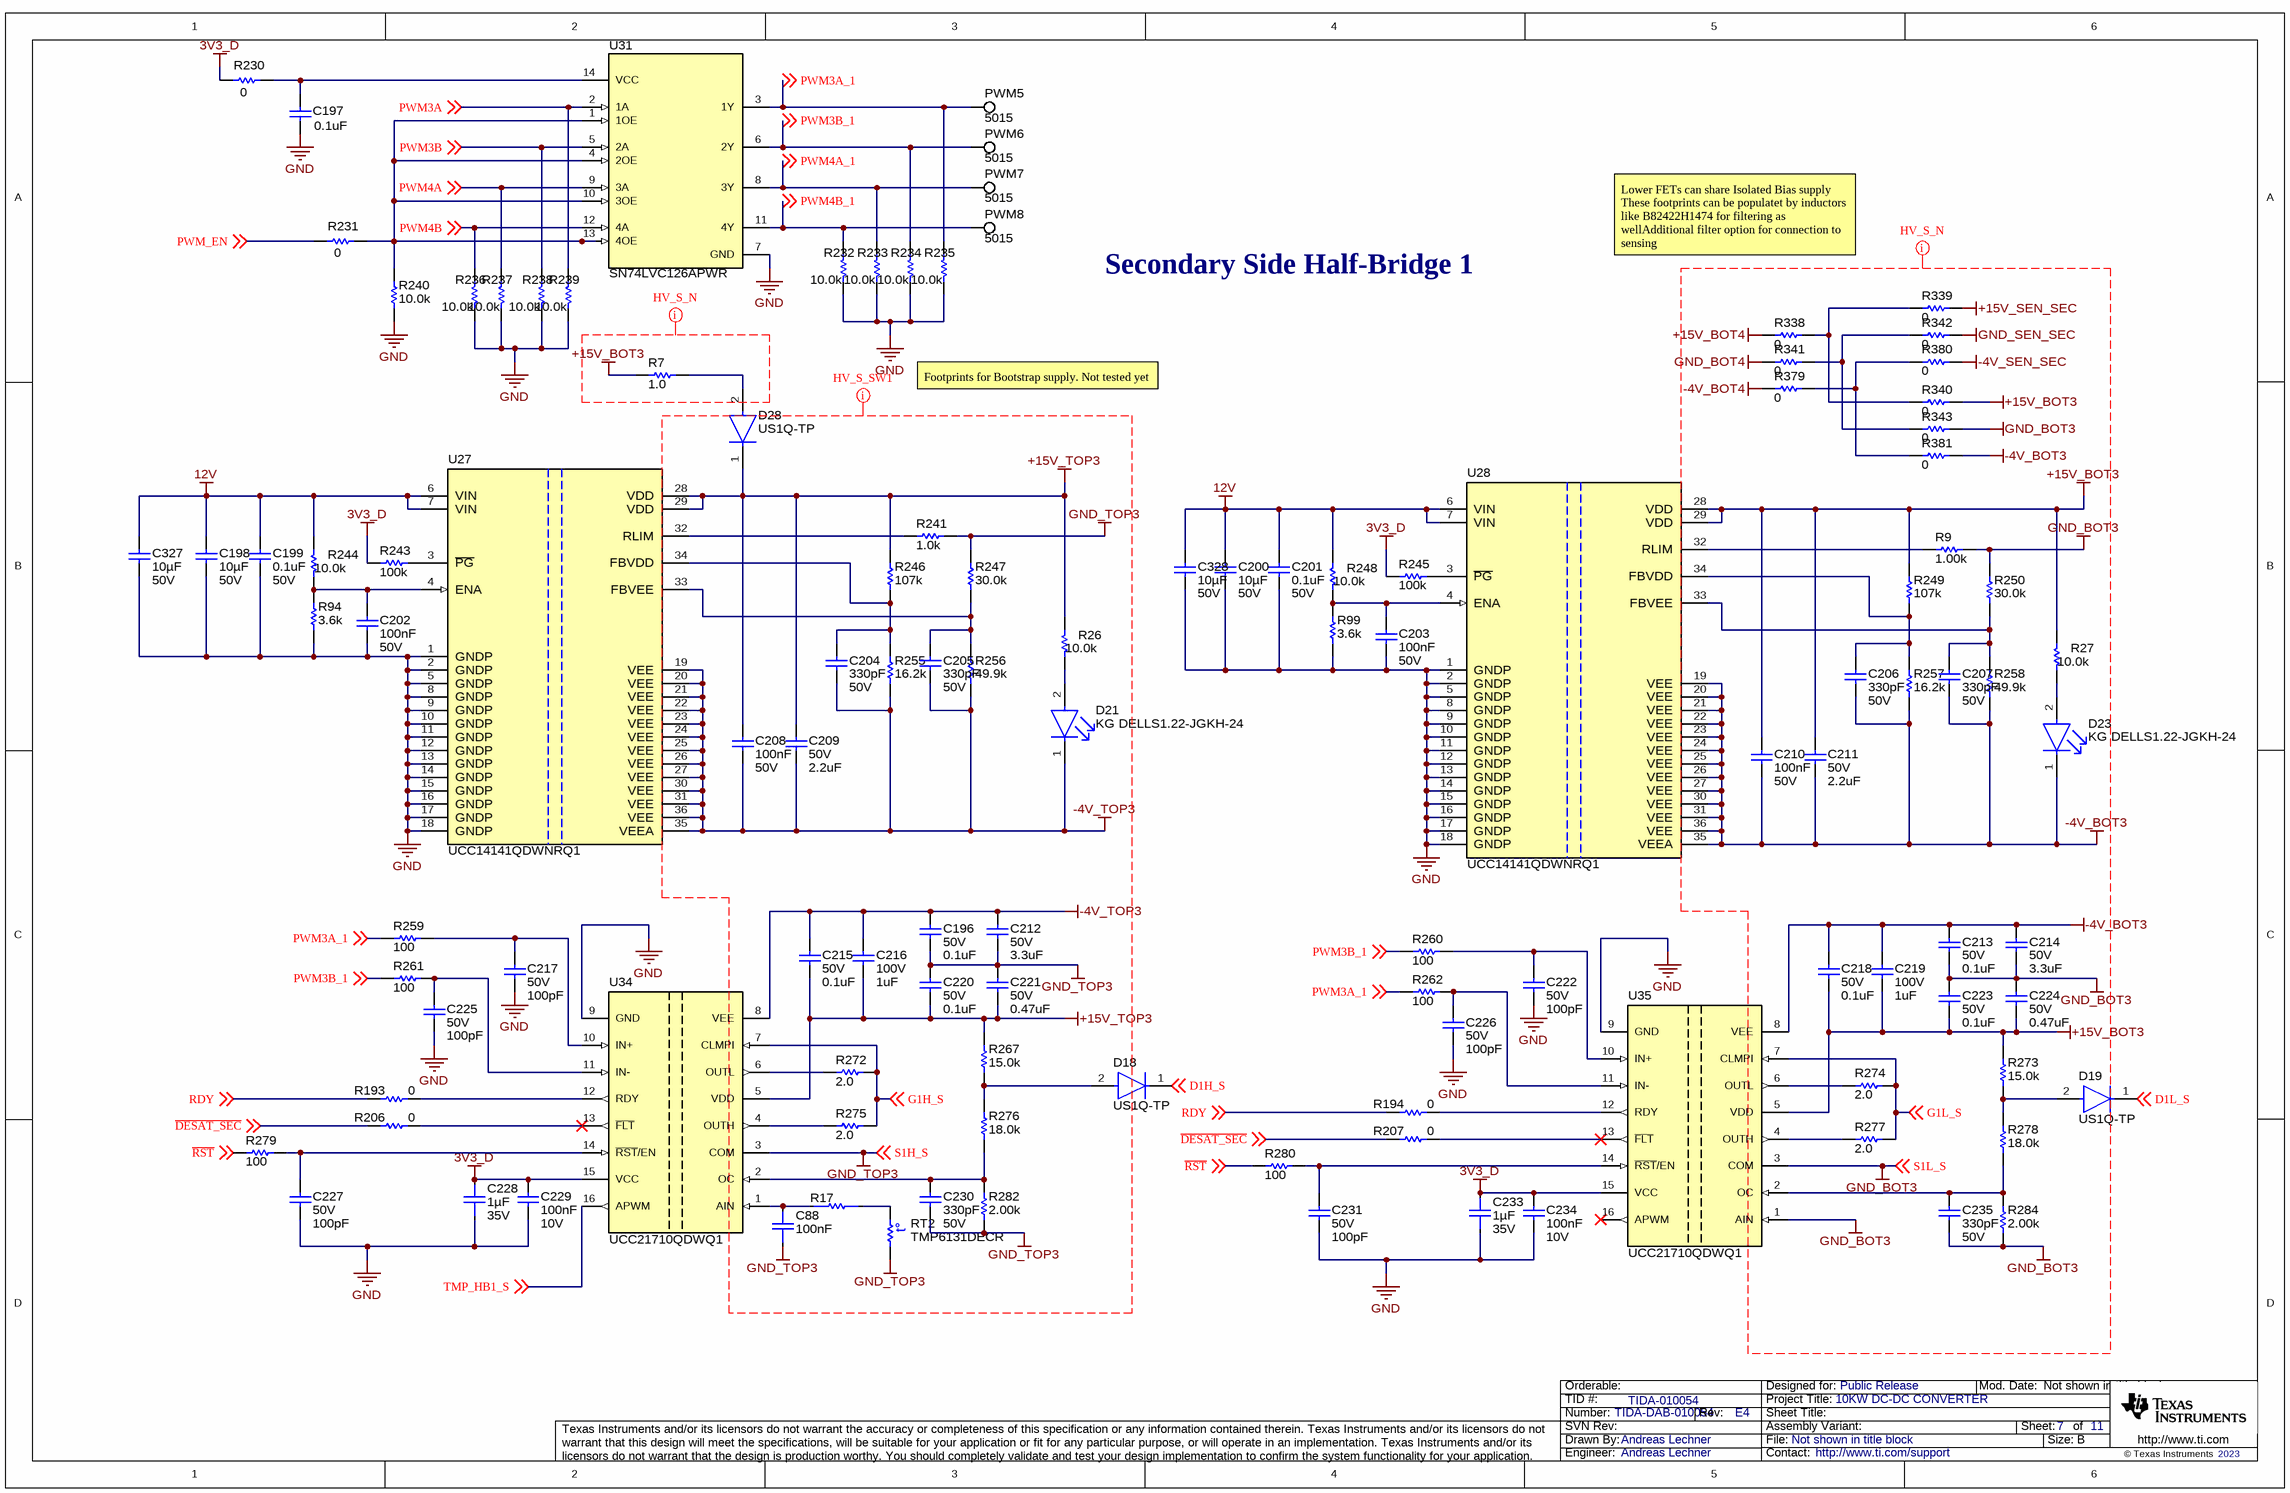
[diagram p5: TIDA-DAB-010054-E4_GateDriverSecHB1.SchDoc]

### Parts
C88  Cap_F: 100nF  [FP-CL10B104KA8VPJC_0603-MFG]  (hidden comment: CL10B104KA8VPJC)
C196  VDC_V: 50V  ValueDisplayed: 0.1uF  [1206L]  (hidden comment: C1206C104K5RACTU)
C197  ValueDisplayed: 0.1uF  [0603]  (hidden comment: 885012206095)
C198  ValueDisplayed: 10µF  VDC_V: 50V  [1206_190L]  (hidden comment: CGA5L1X7R1H106K160AC)
C199  value 0.1uF  VDC_V: 50V  [0603]  (hidden comment: CGA3E2X7R1H104K080AA)
C200  ValueDisplayed: 10µF  VDC_V: 50V  [1206_190L]  (hidden comment: CGA5L1X7R1H106K160AC)
C201  value 0.1uF  VDC_V: 50V  [0603]  (hidden comment: CGA3E2X7R1H104K080AA)
C202  Cap_F: 100nF  VDC_V: 50V  [0603]  (hidden comment: CGA3E2X7R1H104K080AA)
C203  Cap_F: 100nF  VDC_V: 50V  [0603]  (hidden comment: CGA3E2X7R1H104K080AA)
C204  Cap_F: 330pF  VDC_V: 50V  [0603]  (hidden comment: C0603C331K5RACTU)
C205  Cap_F: 330pF  VDC_V: 50V  [0603]  (hidden comment: C0603C331K5RACTU)
C206  Cap_F: 330pF  VDC_V: 50V  [0603]  (hidden comment: C0603C331K5RACTU)
C207  Cap_F: 330pF  VDC_V: 50V  [0603]  (hidden comment: C0603C331K5RACTU)
C208  Cap_F: 100nF  VDC_V: 50V  [0603]  (hidden comment: CGA3E2X7R1H104K080AA)
C209  VDC_V: 50V  ValueDisplayed: 2.2uF  [1206_180L]  (hidden comment: C3216X7R1H225K160AB)
C210  Cap_F: 100nF  VDC_V: 50V  [0603]  (hidden comment: CGA3E2X7R1H104K080AA)
C211  VDC_V: 50V  ValueDisplayed: 2.2uF  [1206_180L]  (hidden comment: C3216X7R1H225K160AB)
C212  VDC_V: 50V  ValueDisplayed: 3.3uF  [1206_180L]  (hidden comment: C3216X5R1H335K160AB)
C213  VDC_V: 50V  ValueDisplayed: 0.1uF  [1206L]  (hidden comment: C1206C104K5RACTU)
C214  VDC_V: 50V  ValueDisplayed: 3.3uF  [1206_180L]  (hidden comment: C3216X5R1H335K160AB)
C215  VDC_V: 50V  ValueDisplayed: 0.1uF  [1206L]  (hidden comment: C1206C104K5RACTU)
C216  VDC_V: 100V  ValueDisplayed: 1uF  [1206_180L]  (hidden comment: C3216X7R2A105K160AA)
C217  VDC_V: 50V  ValueDisplayed: 100pF  [0603]  (hidden comment: C0603C101F5GACTU)
C218  VDC_V: 50V  ValueDisplayed: 0.1uF  [1206L]  (hidden comment: C1206C104K5RACTU)
C219  VDC_V: 100V  ValueDisplayed: 1uF  [1206_180L]  (hidden comment: C3216X7R2A105K160AA)
C220  VDC_V: 50V  ValueDisplayed: 0.1uF  [1206L]  (hidden comment: C1206C104K5RACTU)
C221  VDC_V: 50V  ValueDisplayed: 0.47uF  [1206_180L]  (hidden comment: C3216X7R1H474K160AA)
C222  VDC_V: 50V  ValueDisplayed: 100pF  [0603]  (hidden comment: C0603C101F5GACTU)
C223  VDC_V: 50V  ValueDisplayed: 0.1uF  [1206L]  (hidden comment: C1206C104K5RACTU)
C224  VDC_V: 50V  ValueDisplayed: 0.47uF  [1206_180L]  (hidden comment: C3216X7R1H474K160AA)
C225  VDC_V: 50V  ValueDisplayed: 100pF  [0603]  (hidden comment: C0603C101F5GACTU)
C226  VDC_V: 50V  ValueDisplayed: 100pF  [0603]  (hidden comment: C0603C101F5GACTU)
C227  VDC_V: 50V  ValueDisplayed: 100pF  [0603]  (hidden comment: C0603C101F5GACTU)
C228  Cap_F: 1µF  VDC_V: 35V  [FP-CL10B105KL9VPJC_0603-MFG]  (hidden comment: CL10B105KL9VPJC)
C229  Cap_F: 100nF  VDC_V: 10V  [0603]  (hidden comment: 0603ZC104KAT2A)
C230  Cap_F: 330pF  VDC_V: 50V  [0603]  (hidden comment: C0603C331K5RACTU)
C231  VDC_V: 50V  ValueDisplayed: 100pF  [0603]  (hidden comment: C0603C101F5GACTU)
C233  Cap_F: 1µF  VDC_V: 35V  [FP-CL10B105KL9VPJC_0603-MFG]  (hidden comment: CL10B105KL9VPJC)
C234  Cap_F: 100nF  VDC_V: 10V  [0603]  (hidden comment: 0603ZC104KAT2A)
C235  Cap_F: 330pF  VDC_V: 50V  [0603]  (hidden comment: C0603C331K5RACTU)
C327  ValueDisplayed: 10µF  VDC_V: 50V  [1206_190L]  (hidden comment: CGA5L1X7R1H106K160AC)
C328  ValueDisplayed: 10µF  VDC_V: 50V  [1206_190L]  (hidden comment: CGA5L1X7R1H106K160AC)
D18  US1Q-TP  [FP-US1Q-TP_SMA-MFG]
D19  US1Q-TP  [FP-US1Q-TP_SMA-MFG]
D21  KG DELLS1.22-JGKH-24  [FP-KG DELLS1.22-JGKH-24_0603-MFG]
D23  KG DELLS1.22-JGKH-24  [FP-KG DELLS1.22-JGKH-24_0603-MFG]
D28  US1Q-TP  [FP-US1Q-TP_SMA-MFG]
PWM5  5015  [Testpoint_Keystone_Miniature]
PWM6  5015  [Testpoint_Keystone_Miniature]
PWM7  5015  [Testpoint_Keystone_Miniature]
PWM8  5015  [Testpoint_Keystone_Miniature]
R7  ValueDisplayed: 1.0  [1206]  (hidden comment: CRM1206-JW-1R0ELF)
R9  ValueDisplayed: 1.00k  [0805_HV]  (hidden comment: ERJ-P06F1001V)
R17  CH0603-10RJFTA  [FP-CH0603-10RJFTA_0603-MFG]  (value not drawn)
R26  ValueDisplayed: 10.0k  [0603]  (hidden comment: CRCW060310K0FKEA)
R27  ValueDisplayed: 10.0k  [0603]  (hidden comment: CRCW060310K0FKEA)
R94  ValueDisplayed: 3.6k  [0603]  (hidden comment: RC0603JR-073K6L)
R99  ValueDisplayed: 3.6k  [0603]  (hidden comment: RC0603JR-073K6L)
R193  ValueDisplayed: 0  [0603]  (hidden comment: RMCF0603ZT0R00)
R194  ValueDisplayed: 0  [0603]  (hidden comment: RMCF0603ZT0R00)
R206  ValueDisplayed: 0  [0603]  (hidden comment: RMCF0603ZT0R00)
R207  ValueDisplayed: 0  [0603]  (hidden comment: RMCF0603ZT0R00)
R230  ValueDisplayed: 0  [0603]  (hidden comment: ERJ-3GEY0R00V)
R231  ValueDisplayed: 0  [0603]  (hidden comment: ERJ-3GEY0R00V)
R232  ValueDisplayed: 10.0k  [0603]  (hidden comment: CRCW060310K0FKEA)
R233  ValueDisplayed: 10.0k  [0603]  (hidden comment: CRCW060310K0FKEA)
R234  ValueDisplayed: 10.0k  [0603]  (hidden comment: CRCW060310K0FKEA)
R235  ValueDisplayed: 10.0k  [0603]  (hidden comment: CRCW060310K0FKEA)
R236  ValueDisplayed: 10.0k  [0603]  (hidden comment: CRCW060310K0FKEA)
R237  ValueDisplayed: 10.0k  [0603]  (hidden comment: CRCW060310K0FKEA)
R238  ValueDisplayed: 10.0k  [0603]  (hidden comment: CRCW060310K0FKEA)
R239  ValueDisplayed: 10.0k  [0603]  (hidden comment: CRCW060310K0FKEA)
R240  ValueDisplayed: 10.0k  [0603]  (hidden comment: CRCW060310K0FKEA)
R241  ValueDisplayed: 1.0k  [0603]  (hidden comment: RCA06031K00JNEA)
R243  ValueDisplayed: 100k  [0603]  (hidden comment: CRCW0603100KJNEA)
R244  ValueDisplayed: 10.0k  [0603]  (hidden comment: CRCW060310K0FKEA)
R245  ValueDisplayed: 100k  [0603]  (hidden comment: CRCW0603100KJNEA)
R246  ValueDisplayed: 107k  [0603]  (hidden comment: RT0603BRD07107KL)
R247  ValueDisplayed: 30.0k  [0603]  (hidden comment: RG1608P-303-B-T5)
R248  ValueDisplayed: 10.0k  [0603]  (hidden comment: CRCW060310K0FKEA)
R249  ValueDisplayed: 107k  [0603]  (hidden comment: RT0603BRD07107KL)
R250  ValueDisplayed: 30.0k  [0603]  (hidden comment: RG1608P-303-B-T5)
R255  ValueDisplayed: 16.2k  [0603]  (hidden comment: RT0603BRD0716K2L)
R256  ValueDisplayed: 49.9k  [0603]  (hidden comment: RT0603BRD0749K9L)
R257  ValueDisplayed: 16.2k  [0603]  (hidden comment: RT0603BRD0716K2L)
R258  ValueDisplayed: 49.9k  [0603]  (hidden comment: RT0603BRD0749K9L)
R259  ValueDisplayed: 100  [0603]  (hidden comment: CRCW0603100RJNEA)
R260  ValueDisplayed: 100  [0603]  (hidden comment: CRCW0603100RJNEA)
R261  ValueDisplayed: 100  [0603]  (hidden comment: CRCW0603100RJNEA)
R262  ValueDisplayed: 100  [0603]  (hidden comment: CRCW0603100RJNEA)
R267  ValueDisplayed: 15.0k  [0603]  (hidden comment: RC0603FR-0715KL)
R272  ValueDisplayed: 2.0  [1206]  (hidden comment: CRCW12062R00JNEA)
R273  ValueDisplayed: 15.0k  [0603]  (hidden comment: RC0603FR-0715KL)
R274  ValueDisplayed: 2.0  [1206]  (hidden comment: CRCW12062R00JNEA)
R275  ValueDisplayed: 2.0  [1206]  (hidden comment: CRCW12062R00JNEA)
R276  ValueDisplayed: 18.0k  [0603]  (hidden comment: ERJ3EKF1802V)
R277  ValueDisplayed: 2.0  [1206]  (hidden comment: CRCW12062R00JNEA)
R278  ValueDisplayed: 18.0k  [0603]  (hidden comment: ERJ3EKF1802V)
R279  ValueDisplayed: 100  [0603]  (hidden comment: CRCW0603100RJNEA)
R280  ValueDisplayed: 100  [0603]  (hidden comment: CRCW0603100RJNEA)
R282  ValueDisplayed: 2.00k  [0603]  (hidden comment: RC0603FR-072KL)
R284  ValueDisplayed: 2.00k  [0603]  (hidden comment: RC0603FR-072KL)
R338  ValueDisplayed: 0  [1210]  (hidden comment: CRCW12100000Z0EA)
R339  ValueDisplayed: 0  [1210]  (hidden comment: CRCW12100000Z0EA)
R340  ValueDisplayed: 0  [1210]  (hidden comment: CRCW12100000Z0EA)
R341  ValueDisplayed: 0  [1210]  (hidden comment: CRCW12100000Z0EA)
R342  ValueDisplayed: 0  [1210]  (hidden comment: CRCW12100000Z0EA)
R343  ValueDisplayed: 0  [1210]  (hidden comment: CRCW12100000Z0EA)
R379  ValueDisplayed: 0  [1210]  (hidden comment: CRCW12100000Z0EA)
R380  ValueDisplayed: 0  [1210]  (hidden comment: CRCW12100000Z0EA)
R381  ValueDisplayed: 0  [1210]  (hidden comment: CRCW12100000Z0EA)
RT2  TMP6131DECR  [DEC0002A]
U27  UCC14141QDWNRQ1  [DWJ0036A-MFG]
U28  UCC14141QDWNRQ1  [DWJ0036A-MFG]
U31  SN74LVC126APWR  [PW0014A_N]
U34  UCC21710QDWQ1  [DW0016B_HV]
U35  UCC21710QDWQ1  [DW0016B_HV]

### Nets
3V3_D: C228.2 C229.2 C233.2 C234.2 R230.1 R243.1 R245.1 U34.15(VCC) U35.15(VCC)
12V: C198.1 C199.1 C200.1 C201.1 C327.1 C328.1 R244.2 R248.2 U27.6(VIN) U27.7(VIN) U28.6(VIN) U28.7(VIN)
+15V_BOT3: C210.1 C211.1 C218.2 C219.2 C223.2 C224.2 R7.1 R27.2 R249.2 R273.2 R340.2 U28.28(VDD) U28.29(VDD) U35.5(VDD)
+15V_BOT4: R338.1
+15V_SEN_SEC: R339.2
+15V_TOP3: C208.1 C209.1 C215.2 C216.2 C220.2 C221.2 D28.1(CATHODE) R26.2 R246.2 R267.2 U27.28(VDD) U27.29(VDD) U34.5(VDD)
-4V_BOT3: C206.2 C207.2 C210.2 C211.2 C213.1 C214.1 C218.1 C219.1 D23.1(CATHODE) R257.1 R258.1 R381.2 U28.19(VEE) U28.20(VEE) U28.21(VEE) U28.22(VEE) U28.23(VEE) U28.24(VEE) U28.25(VEE) U28.26(VEE) U28.27(VEE) U28.30(VEE) U28.31(VEE) U28.35(VEEA) U28.36(VEE) U35.8(VEE)
-4V_BOT4: R379.1
-4V_SEN_SEC: R380.2
-4V_TOP3: C196.1 C204.2 C205.2 C208.2 C209.2 C212.1 C215.1 C216.1 D21.1(CATHODE) R255.1 R256.1 U27.19(VEE) U27.20(VEE) U27.21(VEE) U27.22(VEE) U27.23(VEE) U27.24(VEE) U27.25(VEE) U27.26(VEE) U27.27(VEE) U27.30(VEE) U27.31(VEE) U27.35(VEEA) U27.36(VEE) U34.8(VEE)
GND: C197.2 C198.2 C199.2 C200.2 C201.2 C202.2 C203.2 C217.2 C222.2 C225.2 C226.2 C227.2 C228.1 C229.1 C231.2 C233.1 C234.1 C327.2 C328.2 R94.1 R99.1 R232.1 R233.1 R234.1 R235.1 R236.1 R237.1 R238.1 R239.1 R240.1 U27.1(GNDP) U27.2(GNDP) U27.5(GNDP) U27.8(GNDP) U27.9(GNDP) U27.10(GNDP) U27.11(GNDP) U27.12(GNDP) U27.13(GNDP) U27.14(GNDP) U27.15(GNDP) U27.16(GNDP) U27.17(GNDP) U27.18(GNDP) U28.1(GNDP) U28.2(GNDP) U28.5(GNDP) U28.8(GNDP) U28.9(GNDP) U28.10(GNDP) U28.11(GNDP) U28.12(GNDP) U28.13(GNDP) U28.14(GNDP) U28.15(GNDP) U28.16(GNDP) U28.17(GNDP) U28.18(GNDP) U31.7(GND) U34.9(GND) U35.9(GND)
GND_BOT3: C213.2 C214.2 C223.1 C224.1 C235.2 R9.2 R250.2 R284.1 R343.2 U35.1(AIN) U35.3(COM) ; off-sheet S1L_S  [also labelled S1L_S]
GND_BOT4: R341.1
GND_SEN_SEC: R342.2
GND_TOP3: C88.1 C196.2 C212.2 C220.1 C221.1 C230.2 R241.2 R247.2 R282.1 RT2.1 U34.3(COM) ; off-sheet S1H_S  [also labelled S1H_S]
~{DESAT_SEC}: R206.1 R207.1 ; off-sheet ~{DESAT_SEC}
~{RST}: R279.1 R280.1 ; off-sheet ~{RST}
D1H_S: D18.1(CATHODE) ; off-sheet D1H_S
D1L_S: D19.1(CATHODE) ; off-sheet D1L_S
G1H_S: R272.2 R275.2 U34.7(CLMPI) ; off-sheet G1H_S
G1L_S: R274.2 R277.2 U35.7(CLMPI) ; off-sheet G1L_S
PWM3A: R239.2 U31.2(1A) ; off-sheet PWM3A
PWM3A_1: PWM5.1 R235.2 R259.1 R262.1 U31.3(1Y) ; off-sheet PWM3A_1
PWM3B: R238.2 U31.5(2A) ; off-sheet PWM3B
PWM3B_1: PWM6.1 R234.2 R260.1 R261.1 U31.6(2Y) ; off-sheet PWM3B_1
PWM4A: R237.2 U31.9(3A) ; off-sheet PWM4A
PWM4A_1: PWM7.1 R233.2 U31.8(3Y) ; off-sheet PWM4A_1
PWM4B: R236.2 U31.12(4A) ; off-sheet PWM4B
PWM4B_1: PWM8.1 R232.2 U31.11(4Y) ; off-sheet PWM4B_1
PWM_EN: R231.1 ; off-sheet PWM_EN
RDY: R193.1 R194.1 ; off-sheet RDY
TMP_HB1_S: U34.16(APWM) ; off-sheet TMP_HB1_S
NetC88_2: C88.2 R17.1 U34.1(AIN)
NetC197_1: C197.1 R230.2 U31.14(VCC)
NetC202_1: C202.1 R94.2 R244.1 U27.4(ENA)
NetC203_1: C203.1 R99.2 R248.1 U28.4(ENA)
NetC204_1: C204.1 R246.1 R255.2 U27.34(FBVDD)
NetC205_1: C205.1 R247.1 R256.2 U27.33(FBVEE)
NetC206_1: C206.1 R249.1 R257.2 U28.34(FBVDD)
NetC207_1: C207.1 R250.1 R258.2 U28.33(FBVEE)
NetC217_1: C217.1 R259.2 U34.10(IN+)
NetC222_1: C222.1 R260.2 U35.10(IN+)
NetC225_1: C225.1 R261.2 U34.11(IN-)
NetC226_1: C226.1 R262.2 U35.11(IN-)
NetC227_1: C227.1 R279.2 U34.14(~{RST}/EN)
NetC230_1: C230.1 R276.1 R282.2 U34.2(OC)
NetC231_1: C231.1 R280.2 U35.14(~{RST}/EN)
NetC235_1: C235.1 R278.1 R284.2 U35.2(OC)
NetD18_2: D18.2(ANODE) R267.1 R276.2
NetD19_2: D19.2(ANODE) R273.1 R278.2
NetD21_2: D21.2(ANODE) R26.1
NetD23_2: D23.2(ANODE) R27.1
NetD28_2: D28.2(ANODE) R7.2
NetR9_1: R9.1 U28.32(RLIM)
NetR17_2: R17.2 RT2.2
NetR193_2: R193.2 U34.12(RDY)
NetR194_2: R194.2 U35.12(RDY)
NetR206_2: R206.2 U34.13(~{FLT})
NetR207_2: R207.2 U35.13(~{FLT})
NetR231_2: R231.2 R240.2 U31.1(1OE) U31.4(2OE) U31.10(3OE) U31.13(4OE)
NetR241_1: R241.1 U27.32(RLIM)
NetR243_2: R243.2 U27.3(~{PG})
NetR245_2: R245.2 U28.3(~{PG})
NetR272_1: R272.1 U34.6(OUTL)
NetR274_1: R274.1 U35.6(OUTL)
NetR275_1: R275.1 U34.4(OUTH)
NetR277_1: R277.1 U35.4(OUTH)
NetR338_2: R338.2 R339.1 R340.1
NetR341_2: R341.2 R342.1 R343.1
NetR379_2: R379.2 R380.1 R381.1

Not connected (* = marked no-connect by the designer): U35 16(APWM)*

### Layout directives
net class HV_S_SW1: +15V_TOP3, -4V_TOP3, G1H_S, GND_TOP3, S1H_S
net class HV_S_N: +15V_BOT3, +15V_BOT4, +15V_SEN_SEC, -4V_BOT3, -4V_BOT4, -4V_SEN_SEC, G1L_S, GND_BOT3, GND_BOT4, GND_SEN_SEC, S1L_S

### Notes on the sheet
- Secondary Side Half-Bridge 1
- Lower FETs can share Isolated Bias supply
  These footprints can be populatet by inductors  like B82422H1474 for filtering as wellAdditional filter option for connection to sensing
- Footprints for Bootstrap supply. Not tested yet

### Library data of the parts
C88 = CMP-0121051-1: as C94 on sheet TIDA-DAB-010054-E4_GateDriverPrimHB2
C196 C213 C215 C218 C220 C223 = CMP-0008586-2: as C248 on sheet TIDA-DAB-010054-E4_GateDriverPrimHB2
C197 = CMP-0006837-4: CAP, CERM, 0.1 uF, 50 V, +/- 10%, X7R, 0603; Manufacturer: Wurth Elektronik; TaMin_C: -55°C; Polarized: N; SizeAreaWB_mm2: 4.68; Value1: Unknown; U/M: EA; Value: 0.1uF; TaMax_C: 125°C; SizeZ_mm: 1; SizeX_mm: 1.6; SizeY_mm: 0.8; Value2: 50V; SizeArea_mm2: 1.28; CompType: Capacitor; Cap_F: 100nF; AEC Category: Q200
C198 C200 C327 C328 = CMP-0085950-1: as C112 on sheet TIDA-DAB-010054-E4_GateDriverPrimHB2
C199 C201 = CMP-0007078-4: as C113 on sheet TIDA-DAB-010054-E4_GateDriverPrimHB2
C202 C203 C208 C210 = CMP-0007078-4: as C232 on sheet TIDA-DAB-010054-E4_GateDriverPrimHB2
C204-C207 C230 C235 = CMP-0006921-4: as C240-C243 on sheet TIDA-DAB-010054-E4_GateDriverPrimHB2
C209 C211 = CMP-0008698-2: as C245 on sheet TIDA-DAB-010054-E4_GateDriverPrimHB2
C212 C214 = CMP-0008661-2: as C249 on sheet TIDA-DAB-010054-E4_GateDriverPrimHB2
C216 C219 = CMP-0008710-2: as C253 on sheet TIDA-DAB-010054-E4_GateDriverPrimHB2
C217 C222 C225-C227 C231 = CMP-0080091-1: as C254 on sheet TIDA-DAB-010054-E4_GateDriverPrimHB2
C221 C224 = CMP-0008701-2: as C258 on sheet TIDA-DAB-010054-E4_GateDriverPrimHB2
C228 C233 = CMP-0121053-1: as C266 on sheet TIDA-DAB-010054-E4_GateDriverPrimHB2
C229 C234 = CMP-0006815-4: as C268 on sheet TIDA-DAB-010054-E4_GateDriverPrimHB2
D18 D19 D28 = CMP-0095286-1: as D22 on sheet TIDA-DAB-010054-E4_GateDriverPrimHB2
D21 D23 = CMP-0093310-1: as D31 on sheet TIDA-DAB-010054-E4_GateDriverPrimHB2
PWM5-PWM8 = CMP-0055152-2: Test Point, Miniature, SMT; Manufacturer: Keystone Electronics; CT: TRUE; Green_Lifecycle: Active; Green_REACh: Passed; CNHeader: FALSE
R7 = CMP-0018745-2: as R20 on sheet TIDA-DAB-010054-E4_GateDriverPrimHB2
R9 = CMP-0021848-2: as R11 on sheet TIDA-DAB-010054-E4_GateDriverPrimHB2
R17 = CMP-0091849-1: as R18 on sheet TIDA-DAB-010054-E4_GateDriverPrimHB2
R26 R27 R232-R240 R244 R248 = CMP-0021998-4: as R31 on sheet TIDA-DAB-010054-E4_GateDriverPrimHB2
R94 R99 = CMP-0025919-5: as R104 on sheet TIDA-DAB-010054-E4_GateDriverPrimHB2
R193 R194 R206 R207 = CMP-0023343-3: as R210-R213 on sheet TIDA-DAB-010054-E4_GateDriverPrimHB2
R230 R231 = CMP-0025874-4: RES, 0, 5%, 0.1 W, AEC-Q200 Grade 0, 0603; Manufacturer: Panasonic; Value: 0; Value_Code: 0000; Power_W: 100mW; Value2: 0.1W; VDC_V: 50V; TempCo: 600 ppm/C; SizeArea_mm2: 1.28; SizeX_mm: 1.6; SizeY_mm: 0.8; SizeZ_mm: 1; EIA_Code: E24; AEC Category: Q200; AEC Qualified: Y; SizeAreaWB_mm2: 4.68
R241 = CMP-0025946-3: as R288 on sheet TIDA-DAB-010054-E4_GateDriverPrimHB2
R243 R245 = CMP-0025698-4: as R286 on sheet TIDA-DAB-010054-E4_GateDriverPrimHB2
R246 R249 = CMP-0023642-3: as R289 on sheet TIDA-DAB-010054-E4_GateDriverPrimHB2
R247 R250 = CMP-0023508-3: as R290 on sheet TIDA-DAB-010054-E4_GateDriverPrimHB2
R255 R257 = CMP-0023798-3: as R298 on sheet TIDA-DAB-010054-E4_GateDriverPrimHB2
R256 R258 = CMP-0024283-3: as R299 on sheet TIDA-DAB-010054-E4_GateDriverPrimHB2
R259-R262 R279 R280 = CMP-0025700-4: as R303-R306 on sheet TIDA-DAB-010054-E4_GateDriverPrimHB2
R267 R273 = CMP-0022816-5: as R311 on sheet TIDA-DAB-010054-E4_GateDriverPrimHB2
R272 R274 R275 R277 = CMP-0018648-3: as R316 on sheet TIDA-DAB-010054-E4_GateDriverPrimHB2
R276 R278 = CMP-0078662-1: as R320 on sheet TIDA-DAB-010054-E4_GateDriverPrimHB2
R282 R284 = CMP-0023000-5: as R325 on sheet TIDA-DAB-010054-E4_GateDriverPrimHB2
R338-R343 R379-R381 = CMP-0015016-3: as R219 on sheet TIDA-DAB-010054-E4_GateDriverPrimHB2
RT2 = CMP-0084566-1: as RT3 on sheet TIDA-DAB-010054-E4_GateDriverPrimHB2
U27 U28 = CMP-0034067-2: as U32 on sheet TIDA-DAB-010054-E4_GateDriverPrimHB2
U31 = CMP-0066280-1: Quadruple Bus Buffer Gate with 3-State Outputs, PW0014A (TSSOP-14); Manufacturer: Texas Instruments; SizeArea_mm2: 32.0; SizeAreaWB_mm2: 58.8; SizeX_mm: 6.4; SizeY_mm: 5.0; SizeZ_mm: 1.2; CompType: IC; U/M: EA
U34 U35 = CMP-0080534-2: as U37 on sheet TIDA-DAB-010054-E4_GateDriverPrimHB2

## Sheet TIDA-DAB-010054-E4_GateDriverSecHB2.SchDoc
size 431 x 279 mm; Date: Not shown in title block; ApprovedBy: Not shown in title block; CheckedBy: Not shown in title block; Author: Not shown in title block; CompanyName: Not shown in title block; Engineer: Not shown in title block; Organization: Not shown in title block; Address1: Not shown in title block; Address2: Not shown in title block; Address3: Not shown in title block; Address4: Not shown in title block; DocumentNumber: 1; Revision: Use project parameter SCH_Rev; SheetNumber: 8; SheetTotal: 11; PageSetup: Record=PageOptions¦CenterHorizontal=True¦CenterVertical=True¦PrintScale=1.00¦XCorrection=1.00¦YCorrection=1.00¦PrintKind=0¦BorderSize=5000000¦LeftOffset=0¦BottomOffset=0¦Orientation=2¦PaperLength=1000¦PaperWidth=1000¦Scale=100¦PaperSource=15¦PrintQuality=600¦MediaType=1¦DitherType=10¦PaperKind=Letter¦PrintScaleMode=1
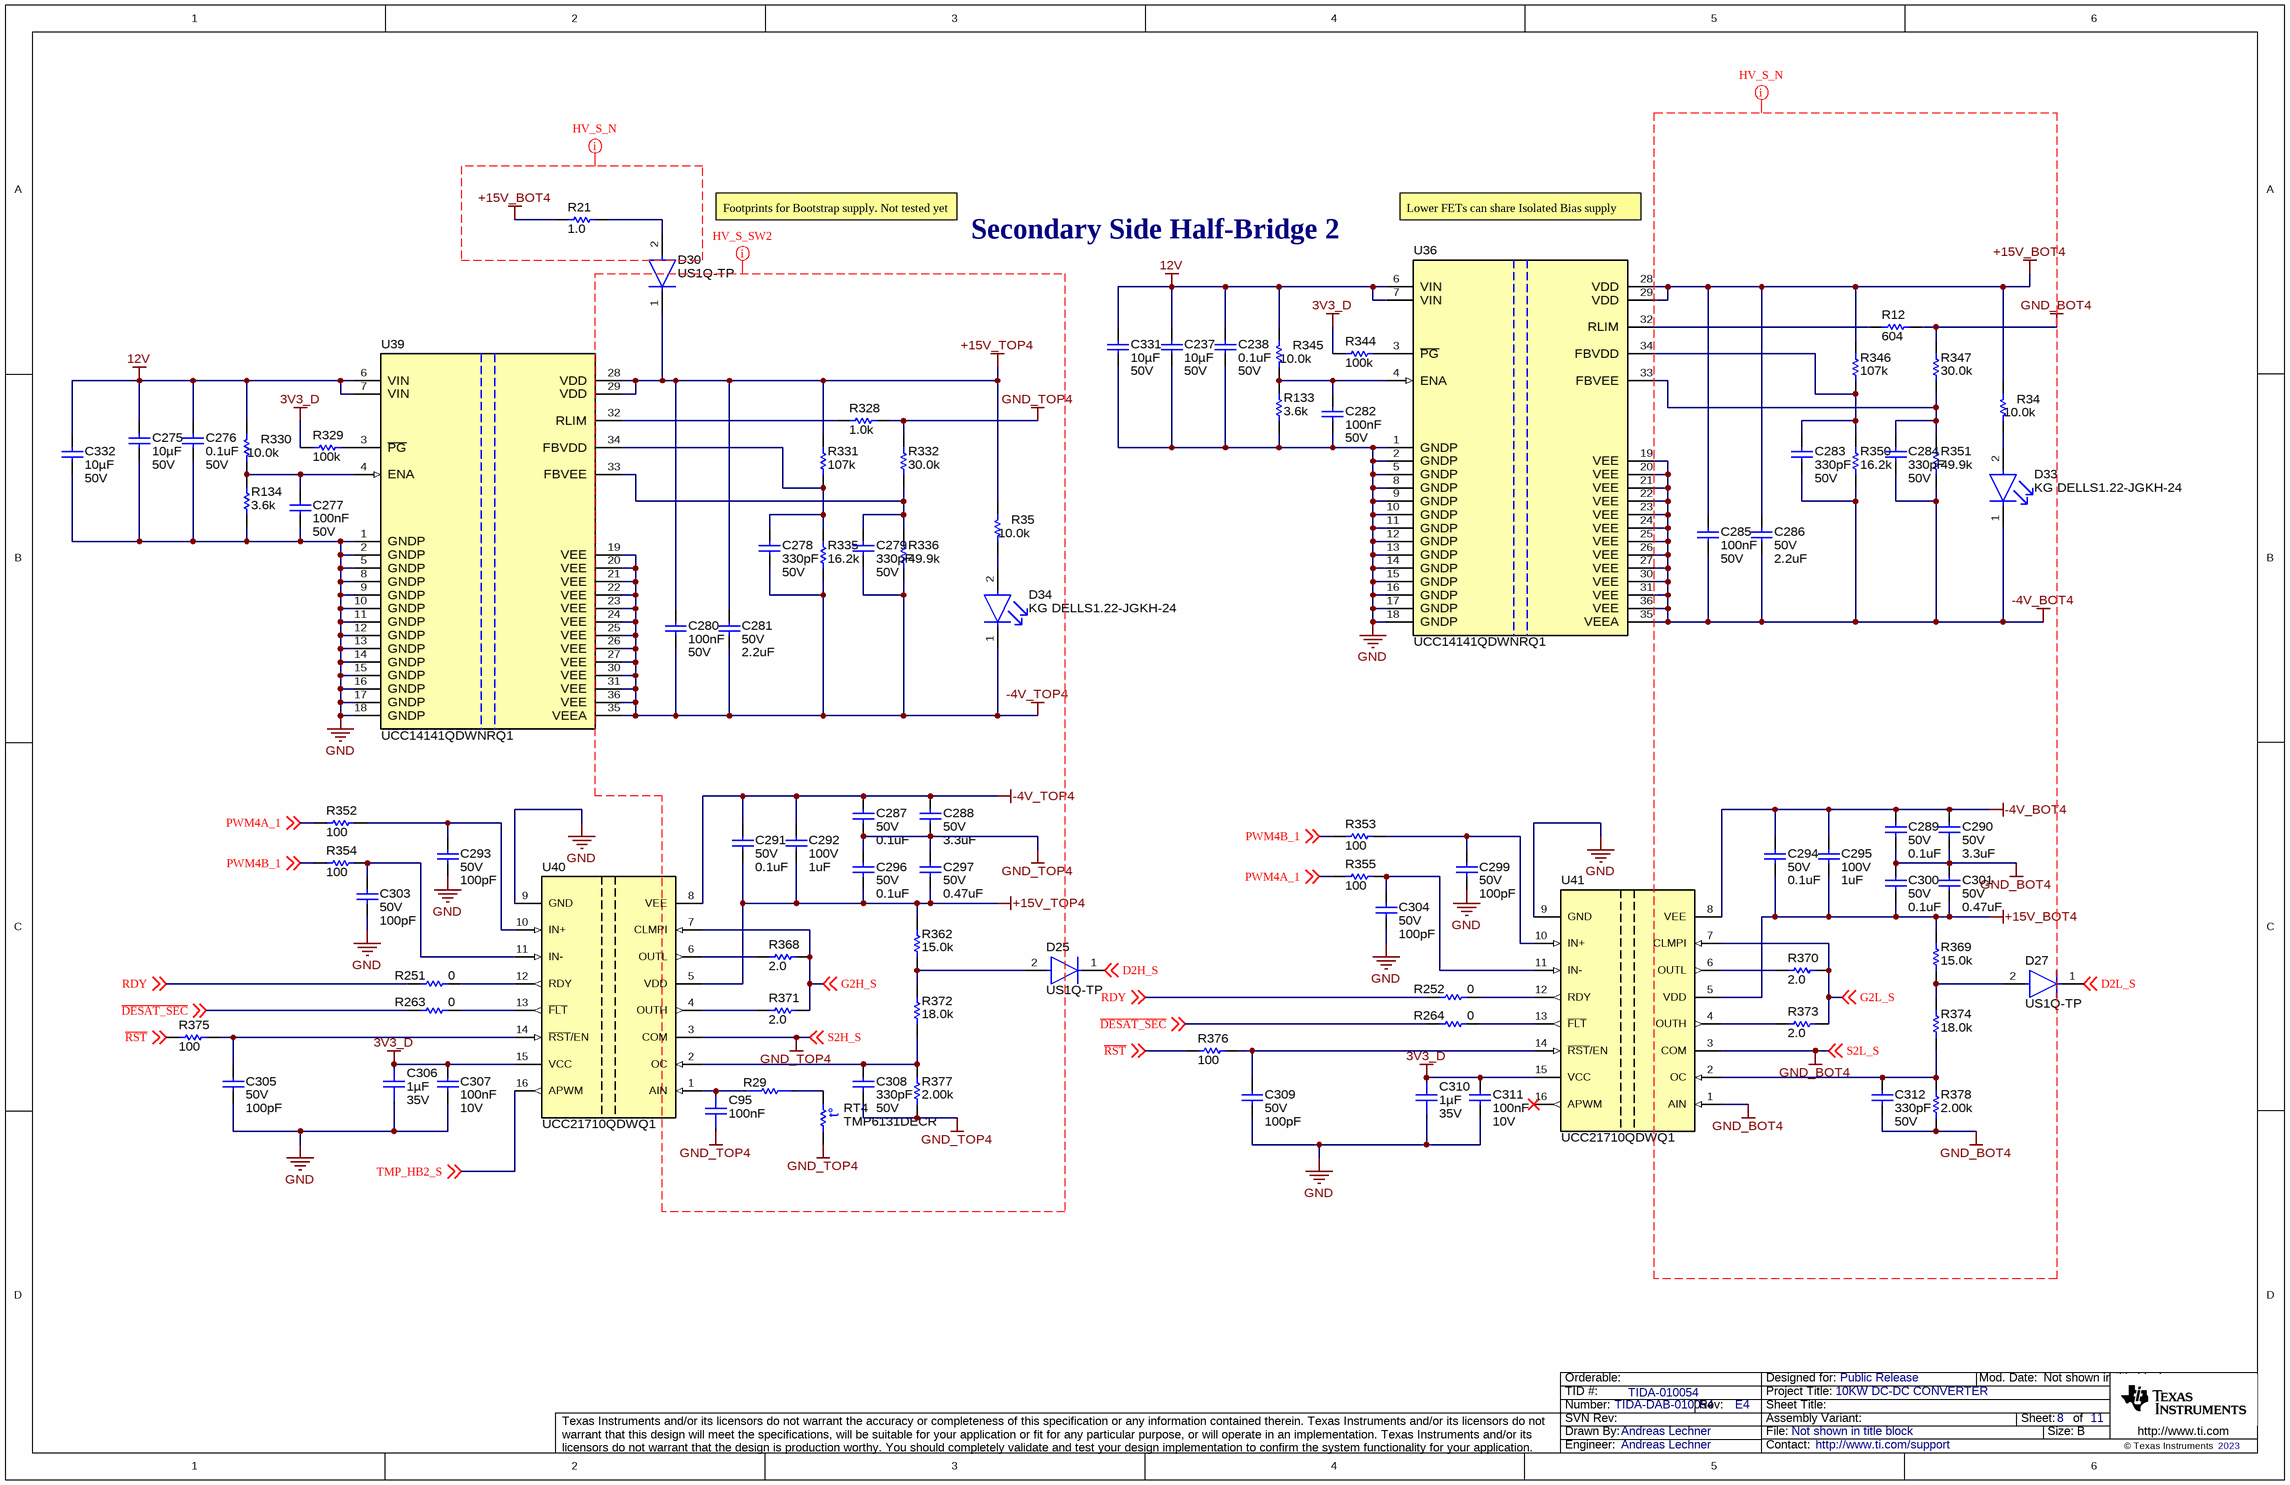
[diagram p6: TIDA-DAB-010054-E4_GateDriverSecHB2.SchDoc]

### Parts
C95  Cap_F: 100nF  [FP-CL10B104KA8VPJC_0603-MFG]  (hidden comment: CL10B104KA8VPJC)
C237  ValueDisplayed: 10µF  VDC_V: 50V  [1206_190L]  (hidden comment: CGA5L1X7R1H106K160AC)
C238  value 0.1uF  VDC_V: 50V  [0603]  (hidden comment: CGA3E2X7R1H104K080AA)
C275  ValueDisplayed: 10µF  VDC_V: 50V  [1206_190L]  (hidden comment: CGA5L1X7R1H106K160AC)
C276  value 0.1uF  VDC_V: 50V  [0603]  (hidden comment: CGA3E2X7R1H104K080AA)
C277  Cap_F: 100nF  VDC_V: 50V  [0603]  (hidden comment: CGA3E2X7R1H104K080AA)
C278  Cap_F: 330pF  VDC_V: 50V  [0603]  (hidden comment: C0603C331K5RACTU)
C279  Cap_F: 330pF  VDC_V: 50V  [0603]  (hidden comment: C0603C331K5RACTU)
C280  Cap_F: 100nF  VDC_V: 50V  [0603]  (hidden comment: CGA3E2X7R1H104K080AA)
C281  VDC_V: 50V  ValueDisplayed: 2.2uF  [1206_180L]  (hidden comment: C3216X7R1H225K160AB)
C282  Cap_F: 100nF  VDC_V: 50V  [0603]  (hidden comment: CGA3E2X7R1H104K080AA)
C283  Cap_F: 330pF  VDC_V: 50V  [0603]  (hidden comment: C0603C331K5RACTU)
C284  Cap_F: 330pF  VDC_V: 50V  [0603]  (hidden comment: C0603C331K5RACTU)
C285  Cap_F: 100nF  VDC_V: 50V  [0603]  (hidden comment: CGA3E2X7R1H104K080AA)
C286  VDC_V: 50V  ValueDisplayed: 2.2uF  [1206_180L]  (hidden comment: C3216X7R1H225K160AB)
C287  VDC_V: 50V  ValueDisplayed: 0.1uF  [1206L]  (hidden comment: C1206C104K5RACTU)
C288  VDC_V: 50V  ValueDisplayed: 3.3uF  [1206_180L]  (hidden comment: C3216X5R1H335K160AB)
C289  VDC_V: 50V  ValueDisplayed: 0.1uF  [1206L]  (hidden comment: C1206C104K5RACTU)
C290  VDC_V: 50V  ValueDisplayed: 3.3uF  [1206_180L]  (hidden comment: C3216X5R1H335K160AB)
C291  VDC_V: 50V  ValueDisplayed: 0.1uF  [1206L]  (hidden comment: C1206C104K5RACTU)
C292  VDC_V: 100V  ValueDisplayed: 1uF  [1206_180L]  (hidden comment: C3216X7R2A105K160AA)
C293  VDC_V: 50V  ValueDisplayed: 100pF  [0603]  (hidden comment: C0603C101F5GACTU)
C294  VDC_V: 50V  ValueDisplayed: 0.1uF  [1206L]  (hidden comment: C1206C104K5RACTU)
C295  VDC_V: 100V  ValueDisplayed: 1uF  [1206_180L]  (hidden comment: C3216X7R2A105K160AA)
C296  VDC_V: 50V  ValueDisplayed: 0.1uF  [1206L]  (hidden comment: C1206C104K5RACTU)
C297  VDC_V: 50V  ValueDisplayed: 0.47uF  [1206_180L]  (hidden comment: C3216X7R1H474K160AA)
C299  VDC_V: 50V  ValueDisplayed: 100pF  [0603]  (hidden comment: C0603C101F5GACTU)
C300  VDC_V: 50V  ValueDisplayed: 0.1uF  [1206L]  (hidden comment: C1206C104K5RACTU)
C301  VDC_V: 50V  ValueDisplayed: 0.47uF  [1206_180L]  (hidden comment: C3216X7R1H474K160AA)
C303  VDC_V: 50V  ValueDisplayed: 100pF  [0603]  (hidden comment: C0603C101F5GACTU)
C304  VDC_V: 50V  ValueDisplayed: 100pF  [0603]  (hidden comment: C0603C101F5GACTU)
C305  VDC_V: 50V  ValueDisplayed: 100pF  [0603]  (hidden comment: C0603C101F5GACTU)
C306  Cap_F: 1µF  VDC_V: 35V  [FP-CL10B105KL9VPJC_0603-MFG]  (hidden comment: CL10B105KL9VPJC)
C307  Cap_F: 100nF  VDC_V: 10V  [0603]  (hidden comment: 0603ZC104KAT2A)
C308  Cap_F: 330pF  VDC_V: 50V  [0603]  (hidden comment: C0603C331K5RACTU)
C309  VDC_V: 50V  ValueDisplayed: 100pF  [0603]  (hidden comment: C0603C101F5GACTU)
C310  Cap_F: 1µF  VDC_V: 35V  [FP-CL10B105KL9VPJC_0603-MFG]  (hidden comment: CL10B105KL9VPJC)
C311  Cap_F: 100nF  VDC_V: 10V  [0603]  (hidden comment: 0603ZC104KAT2A)
C312  Cap_F: 330pF  VDC_V: 50V  [0603]  (hidden comment: C0603C331K5RACTU)
C331  ValueDisplayed: 10µF  VDC_V: 50V  [1206_190L]  (hidden comment: CGA5L1X7R1H106K160AC)
C332  ValueDisplayed: 10µF  VDC_V: 50V  [1206_190L]  (hidden comment: CGA5L1X7R1H106K160AC)
D25  US1Q-TP  [FP-US1Q-TP_SMA-MFG]
D27  US1Q-TP  [FP-US1Q-TP_SMA-MFG]
D30  US1Q-TP  [FP-US1Q-TP_SMA-MFG]
D33  KG DELLS1.22-JGKH-24  [FP-KG DELLS1.22-JGKH-24_0603-MFG]
D34  KG DELLS1.22-JGKH-24  [FP-KG DELLS1.22-JGKH-24_0603-MFG]
R12  ValueDisplayed: 604  [0805_HV]  (hidden comment: ERJ-P06F6040V)
R21  ValueDisplayed: 1.0  [1206]  (hidden comment: CRM1206-JW-1R0ELF)
R29  CH0603-10RJFTA  [FP-CH0603-10RJFTA_0603-MFG]  (value not drawn)
R34  ValueDisplayed: 10.0k  [0603]  (hidden comment: CRCW060310K0FKEA)
R35  ValueDisplayed: 10.0k  [0603]  (hidden comment: CRCW060310K0FKEA)
R133  ValueDisplayed: 3.6k  [0603]  (hidden comment: RC0603JR-073K6L)
R134  ValueDisplayed: 3.6k  [0603]  (hidden comment: RC0603JR-073K6L)
R251  ValueDisplayed: 0  [0603]  (hidden comment: RMCF0603ZT0R00)
R252  ValueDisplayed: 0  [0603]  (hidden comment: RMCF0603ZT0R00)
R263  ValueDisplayed: 0  [0603]  (hidden comment: RMCF0603ZT0R00)
R264  ValueDisplayed: 0  [0603]  (hidden comment: RMCF0603ZT0R00)
R328  ValueDisplayed: 1.0k  [0603]  (hidden comment: RCA06031K00JNEA)
R329  ValueDisplayed: 100k  [0603]  (hidden comment: CRCW0603100KJNEA)
R330  ValueDisplayed: 10.0k  [0603]  (hidden comment: CRCW060310K0FKEA)
R331  ValueDisplayed: 107k  [0603]  (hidden comment: RT0603BRD07107KL)
R332  ValueDisplayed: 30.0k  [0603]  (hidden comment: RG1608P-303-B-T5)
R335  ValueDisplayed: 16.2k  [0603]  (hidden comment: RT0603BRD0716K2L)
R336  ValueDisplayed: 49.9k  [0603]  (hidden comment: RT0603BRD0749K9L)
R344  ValueDisplayed: 100k  [0603]  (hidden comment: CRCW0603100KJNEA)
R345  ValueDisplayed: 10.0k  [0603]  (hidden comment: CRCW060310K0FKEA)
R346  ValueDisplayed: 107k  [0603]  (hidden comment: RT0603BRD07107KL)
R347  ValueDisplayed: 30.0k  [0603]  (hidden comment: RG1608P-303-B-T5)
R350  ValueDisplayed: 16.2k  [0603]  (hidden comment: RT0603BRD0716K2L)
R351  ValueDisplayed: 49.9k  [0603]  (hidden comment: RT0603BRD0749K9L)
R352  ValueDisplayed: 100  [0603]  (hidden comment: CRCW0603100RJNEA)
R353  ValueDisplayed: 100  [0603]  (hidden comment: CRCW0603100RJNEA)
R354  ValueDisplayed: 100  [0603]  (hidden comment: CRCW0603100RJNEA)
R355  ValueDisplayed: 100  [0603]  (hidden comment: CRCW0603100RJNEA)
R362  ValueDisplayed: 15.0k  [0603]  (hidden comment: RC0603FR-0715KL)
R368  ValueDisplayed: 2.0  [1206]  (hidden comment: CRCW12062R00JNEA)
R369  ValueDisplayed: 15.0k  [0603]  (hidden comment: RC0603FR-0715KL)
R370  ValueDisplayed: 2.0  [1206]  (hidden comment: CRCW12062R00JNEA)
R371  ValueDisplayed: 2.0  [1206]  (hidden comment: CRCW12062R00JNEA)
R372  ValueDisplayed: 18.0k  [0603]  (hidden comment: ERJ3EKF1802V)
R373  ValueDisplayed: 2.0  [1206]  (hidden comment: CRCW12062R00JNEA)
R374  ValueDisplayed: 18.0k  [0603]  (hidden comment: ERJ3EKF1802V)
R375  ValueDisplayed: 100  [0603]  (hidden comment: CRCW0603100RJNEA)
R376  ValueDisplayed: 100  [0603]  (hidden comment: CRCW0603100RJNEA)
R377  ValueDisplayed: 2.00k  [0603]  (hidden comment: RC0603FR-072KL)
R378  ValueDisplayed: 2.00k  [0603]  (hidden comment: RC0603FR-072KL)
RT4  TMP6131DECR  [DEC0002A]
U36  UCC14141QDWNRQ1  [DWJ0036A-MFG]
U39  UCC14141QDWNRQ1  [DWJ0036A-MFG]
U40  UCC21710QDWQ1  [DW0016B_HV]
U41  UCC21710QDWQ1  [DW0016B_HV]

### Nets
3V3_D: C306.2 C307.2 C310.2 C311.2 R329.1 R344.1 U40.15(VCC) U41.15(VCC)
12V: C237.1 C238.1 C275.1 C276.1 C331.1 C332.1 R330.2 R345.2 U36.6(VIN) U36.7(VIN) U39.6(VIN) U39.7(VIN)
+15V_BOT4: C285.1 C286.1 C294.2 C295.2 C300.2 C301.2 R21.1 R34.2 R346.2 R369.2 U36.28(VDD) U36.29(VDD) U41.5(VDD)
+15V_TOP4: C280.1 C281.1 C291.2 C292.2 C296.2 C297.2 D30.1(CATHODE) R35.2 R331.2 R362.2 U39.28(VDD) U39.29(VDD) U40.5(VDD)
-4V_BOT4: C283.2 C284.2 C285.2 C286.2 C289.1 C290.1 C294.1 C295.1 D33.1(CATHODE) R350.1 R351.1 U36.19(VEE) U36.20(VEE) U36.21(VEE) U36.22(VEE) U36.23(VEE) U36.24(VEE) U36.25(VEE) U36.26(VEE) U36.27(VEE) U36.30(VEE) U36.31(VEE) U36.35(VEEA) U36.36(VEE) U41.8(VEE)
-4V_TOP4: C278.2 C279.2 C280.2 C281.2 C287.1 C288.1 C291.1 C292.1 D34.1(CATHODE) R335.1 R336.1 U39.19(VEE) U39.20(VEE) U39.21(VEE) U39.22(VEE) U39.23(VEE) U39.24(VEE) U39.25(VEE) U39.26(VEE) U39.27(VEE) U39.30(VEE) U39.31(VEE) U39.35(VEEA) U39.36(VEE) U40.8(VEE)
GND: C237.2 C238.2 C275.2 C276.2 C277.2 C282.2 C293.2 C299.2 C303.2 C304.2 C305.2 C306.1 C307.1 C309.2 C310.1 C311.1 C331.2 C332.2 R133.1 R134.1 U36.1(GNDP) U36.2(GNDP) U36.5(GNDP) U36.8(GNDP) U36.9(GNDP) U36.10(GNDP) U36.11(GNDP) U36.12(GNDP) U36.13(GNDP) U36.14(GNDP) U36.15(GNDP) U36.16(GNDP) U36.17(GNDP) U36.18(GNDP) U39.1(GNDP) U39.2(GNDP) U39.5(GNDP) U39.8(GNDP) U39.9(GNDP) U39.10(GNDP) U39.11(GNDP) U39.12(GNDP) U39.13(GNDP) U39.14(GNDP) U39.15(GNDP) U39.16(GNDP) U39.17(GNDP) U39.18(GNDP) U40.9(GND) U41.9(GND)
GND_BOT4: C289.2 C290.2 C300.1 C301.1 C312.2 R12.2 R347.2 R378.1 U41.1(AIN) U41.3(COM) ; off-sheet S2L_S  [also labelled S2L_S]
GND_TOP4: C95.1 C287.2 C288.2 C296.1 C297.1 C308.2 R328.2 R332.2 R377.1 RT4.1 U40.3(COM) ; off-sheet S2H_S  [also labelled S2H_S]
~{DESAT_SEC}: R263.1 R264.1 ; off-sheet ~{DESAT_SEC}
~{RST}: R375.1 R376.1 ; off-sheet ~{RST}
D2H_S: D25.1(CATHODE) ; off-sheet D2H_S  [project net D1H_S]
D2L_S: D27.1(CATHODE) ; off-sheet D2L_S
G2H_S: R368.2 R371.2 U40.7(CLMPI) ; off-sheet G2H_S
G2L_S: R370.2 R373.2 U41.7(CLMPI) ; off-sheet G2L_S
PWM4A_1: R352.1 R355.1 ; off-sheet PWM4A_1
PWM4B_1: R353.1 R354.1 ; off-sheet PWM4B_1
RDY: R251.1 R252.1 ; off-sheet RDY
TMP_HB2_S: U40.16(APWM) ; off-sheet TMP_HB2_S
NetC95_2: C95.2 R29.1 U40.1(AIN)
NetC277_1: C277.1 R134.2 R330.1 U39.4(ENA)
NetC278_1: C278.1 R331.1 R335.2 U39.34(FBVDD)
NetC279_1: C279.1 R332.1 R336.2 U39.33(FBVEE)
NetC282_1: C282.1 R133.2 R345.1 U36.4(ENA)
NetC283_1: C283.1 R346.1 R350.2 U36.34(FBVDD)
NetC284_1: C284.1 R347.1 R351.2 U36.33(FBVEE)
NetC293_1: C293.1 R352.2 U40.10(IN+)
NetC299_1: C299.1 R353.2 U41.10(IN+)
NetC303_1: C303.1 R354.2 U40.11(IN-)
NetC304_1: C304.1 R355.2 U41.11(IN-)
NetC305_1: C305.1 R375.2 U40.14(~{RST}/EN)
NetC308_1: C308.1 R372.1 R377.2 U40.2(OC)
NetC309_1: C309.1 R376.2 U41.14(~{RST}/EN)
NetC312_1: C312.1 R374.1 R378.2 U41.2(OC)
NetD25_2: D25.2(ANODE) R362.1 R372.2
NetD27_2: D27.2(ANODE) R369.1 R374.2
NetD30_2: D30.2(ANODE) R21.2
NetD33_2: D33.2(ANODE) R34.1
NetD34_2: D34.2(ANODE) R35.1
NetR12_1: R12.1 U36.32(RLIM)
NetR29_2: R29.2 RT4.2
NetR251_2: R251.2 U40.12(RDY)
NetR252_2: R252.2 U41.12(RDY)
NetR263_2: R263.2 U40.13(~{FLT})
NetR264_2: R264.2 U41.13(~{FLT})
NetR328_1: R328.1 U39.32(RLIM)
NetR329_2: R329.2 U39.3(~{PG})
NetR344_2: R344.2 U36.3(~{PG})
NetR368_1: R368.1 U40.6(OUTL)
NetR370_1: R370.1 U41.6(OUTL)
NetR371_1: R371.1 U40.4(OUTH)
NetR373_1: R373.1 U41.4(OUTH)

Not connected (* = marked no-connect by the designer): U41 16(APWM)*

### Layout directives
net class HV_S_SW2: +15V_TOP4, -4V_TOP4, G2H_S, GND_TOP4, S2H_S
net class HV_S_N: +15V_BOT4, -4V_BOT4, G2L_S, GND_BOT4, S2L_S

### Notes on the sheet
- Footprints for Bootstrap supply. Not tested yet
- Lower FETs can share Isolated Bias supply
- Secondary Side Half-Bridge 2

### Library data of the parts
C95 = CMP-0121051-1: as C94 on sheet TIDA-DAB-010054-E4_GateDriverPrimHB2
C237 C275 C331 C332 = CMP-0085950-1: as C112 on sheet TIDA-DAB-010054-E4_GateDriverPrimHB2
C238 C276 = CMP-0007078-4: as C113 on sheet TIDA-DAB-010054-E4_GateDriverPrimHB2
C277 C280 C282 C285 = CMP-0007078-4: as C232 on sheet TIDA-DAB-010054-E4_GateDriverPrimHB2
C278 C279 C283 C284 C308 C312 = CMP-0006921-4: as C240-C243 on sheet TIDA-DAB-010054-E4_GateDriverPrimHB2
C281 C286 = CMP-0008698-2: as C245 on sheet TIDA-DAB-010054-E4_GateDriverPrimHB2
C287 C289 C291 C294 C296 C300 = CMP-0008586-2: as C248 on sheet TIDA-DAB-010054-E4_GateDriverPrimHB2
C288 C290 = CMP-0008661-2: as C249 on sheet TIDA-DAB-010054-E4_GateDriverPrimHB2
C292 C295 = CMP-0008710-2: as C253 on sheet TIDA-DAB-010054-E4_GateDriverPrimHB2
C293 C299 C303-C305 C309 = CMP-0080091-1: as C254 on sheet TIDA-DAB-010054-E4_GateDriverPrimHB2
C297 C301 = CMP-0008701-2: as C258 on sheet TIDA-DAB-010054-E4_GateDriverPrimHB2
C306 C310 = CMP-0121053-1: as C266 on sheet TIDA-DAB-010054-E4_GateDriverPrimHB2
C307 C311 = CMP-0006815-4: as C268 on sheet TIDA-DAB-010054-E4_GateDriverPrimHB2
D25 D27 D30 = CMP-0095286-1: as D22 on sheet TIDA-DAB-010054-E4_GateDriverPrimHB2
D33 D34 = CMP-0093310-1: as D31 on sheet TIDA-DAB-010054-E4_GateDriverPrimHB2
R12 = CMP-0021853-2: RES, 604, 1%, 0.5 W, 0805; Manufacturer: Panasonic; Power_W: 500mW; TempCo: 100 ppm/C; Value_Code: 604R; U/M: EA; Value: 604; EIA_Code: E96; SizeX_mm: 2; SizeY_mm: 1.25; SizeZ_mm: 1.45; Value2: 0.5W; SizeArea_mm2: 2.5; AEC Qualified: N; VDC_V: 400V; AEC Category: Q200
R21 = CMP-0018745-2: as R20 on sheet TIDA-DAB-010054-E4_GateDriverPrimHB2
R29 = CMP-0091849-1: as R18 on sheet TIDA-DAB-010054-E4_GateDriverPrimHB2
R34 R35 R330 R345 = CMP-0021998-4: as R31 on sheet TIDA-DAB-010054-E4_GateDriverPrimHB2
R133 R134 = CMP-0025919-5: as R104 on sheet TIDA-DAB-010054-E4_GateDriverPrimHB2
R251 R252 R263 R264 = CMP-0023343-3: as R210-R213 on sheet TIDA-DAB-010054-E4_GateDriverPrimHB2
R328 = CMP-0025946-3: as R288 on sheet TIDA-DAB-010054-E4_GateDriverPrimHB2
R329 R344 = CMP-0025698-4: as R286 on sheet TIDA-DAB-010054-E4_GateDriverPrimHB2
R331 R346 = CMP-0023642-3: as R289 on sheet TIDA-DAB-010054-E4_GateDriverPrimHB2
R332 R347 = CMP-0023508-3: as R290 on sheet TIDA-DAB-010054-E4_GateDriverPrimHB2
R335 R350 = CMP-0023798-3: as R298 on sheet TIDA-DAB-010054-E4_GateDriverPrimHB2
R336 R351 = CMP-0024283-3: as R299 on sheet TIDA-DAB-010054-E4_GateDriverPrimHB2
R352-R355 R375 R376 = CMP-0025700-4: as R303-R306 on sheet TIDA-DAB-010054-E4_GateDriverPrimHB2
R362 R369 = CMP-0022816-5: as R311 on sheet TIDA-DAB-010054-E4_GateDriverPrimHB2
R368 R370 R371 R373 = CMP-0018648-3: as R316 on sheet TIDA-DAB-010054-E4_GateDriverPrimHB2
R372 R374 = CMP-0078662-1: as R320 on sheet TIDA-DAB-010054-E4_GateDriverPrimHB2
R377 R378 = CMP-0023000-5: as R325 on sheet TIDA-DAB-010054-E4_GateDriverPrimHB2
RT4 = CMP-0084566-1: as RT3 on sheet TIDA-DAB-010054-E4_GateDriverPrimHB2
U36 U39 = CMP-0034067-2: as U32 on sheet TIDA-DAB-010054-E4_GateDriverPrimHB2
U40 U41 = CMP-0080534-2: as U37 on sheet TIDA-DAB-010054-E4_GateDriverPrimHB2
